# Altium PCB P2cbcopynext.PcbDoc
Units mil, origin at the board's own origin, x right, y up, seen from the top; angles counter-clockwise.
Board outline 1574.8 x 1456.69 mil, 4 copper layers (Top Layer, Layer 1, Layer 2, Bottom Layer), stack 23.756 mil thick; 64 components, 49 nets, 255 pads, 114 vias.
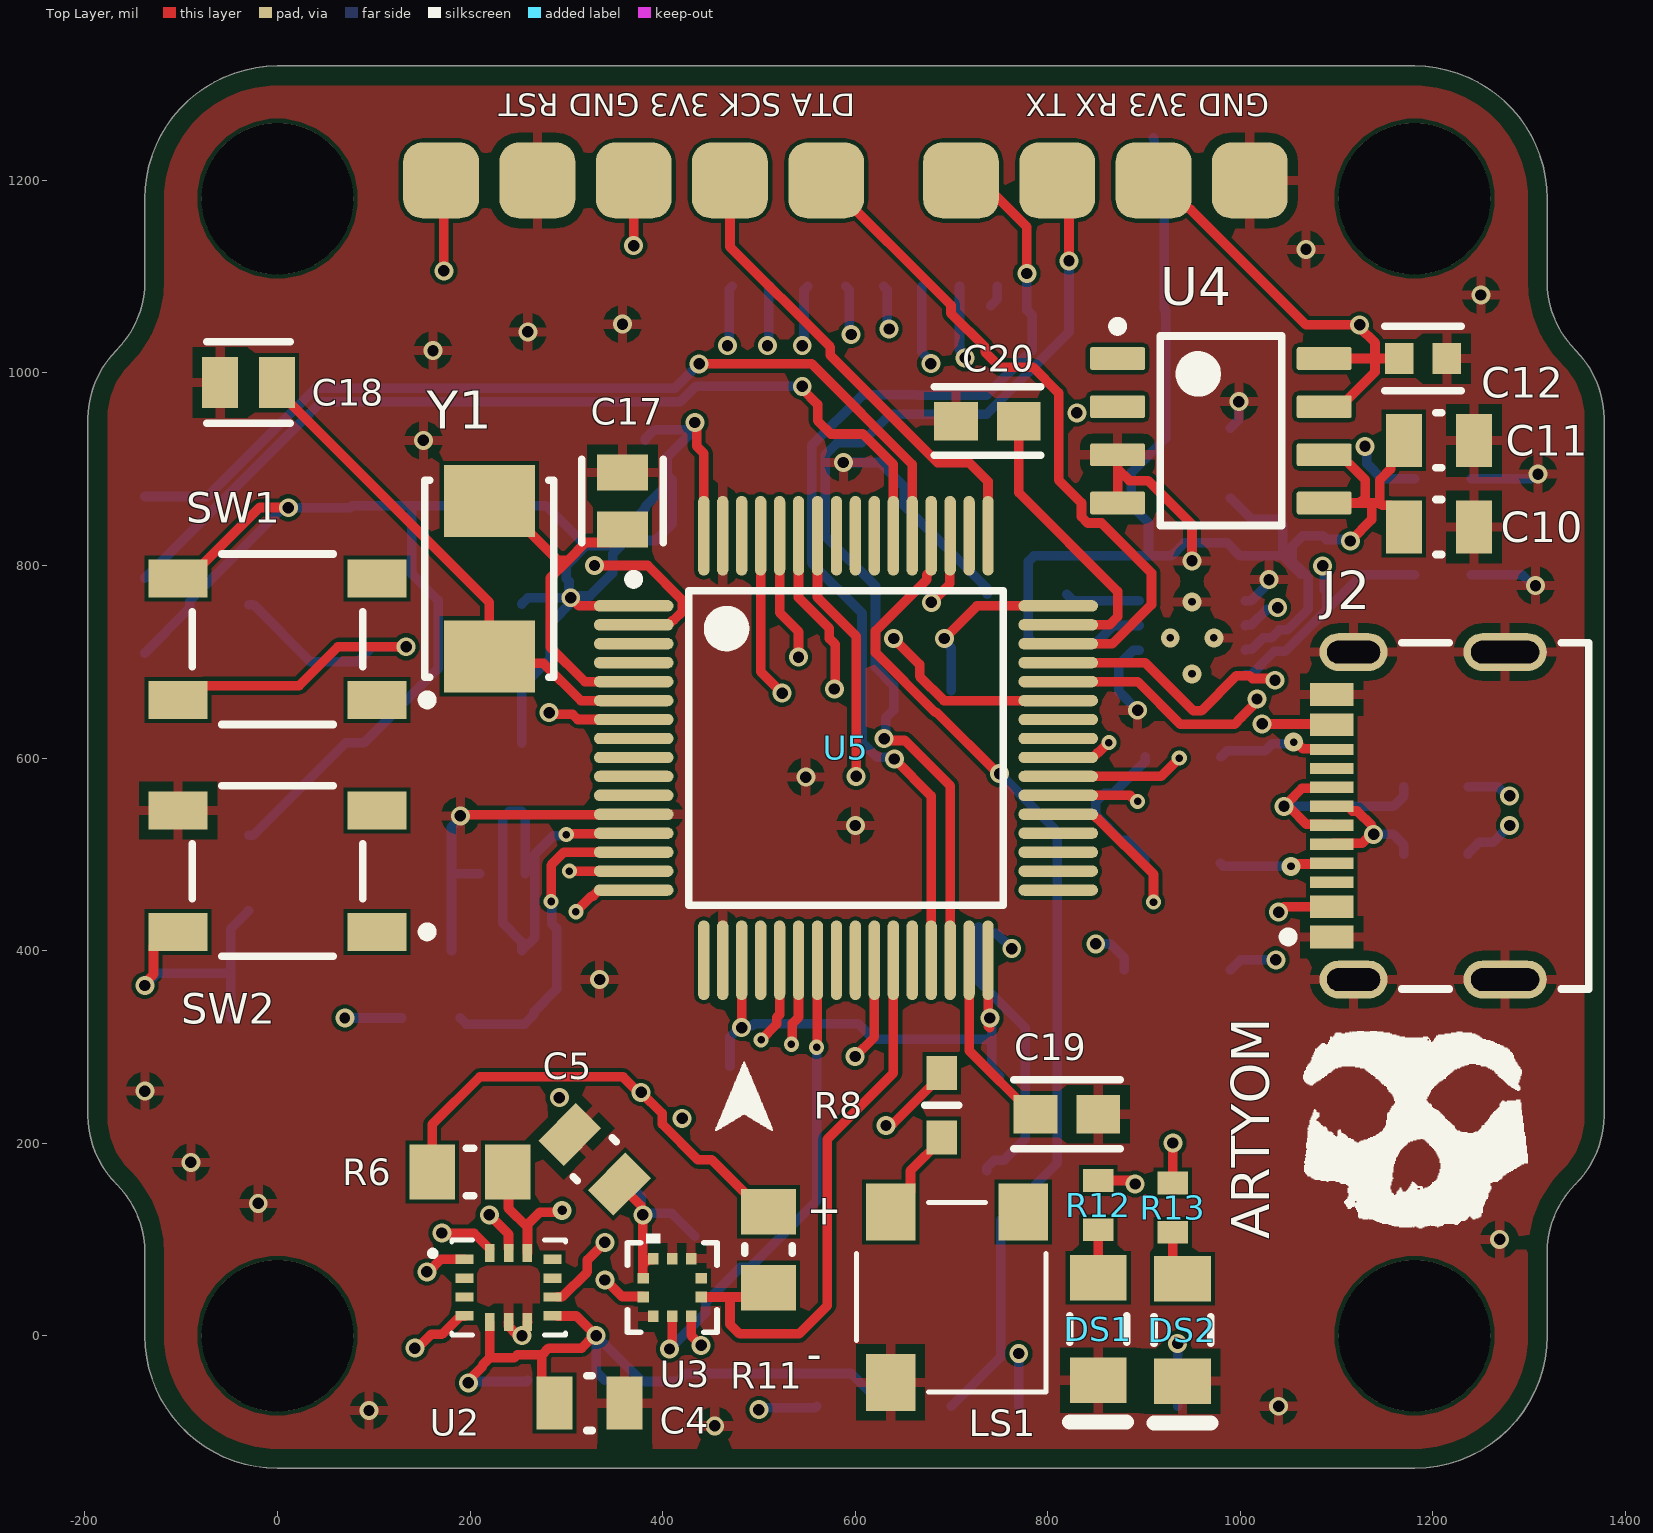
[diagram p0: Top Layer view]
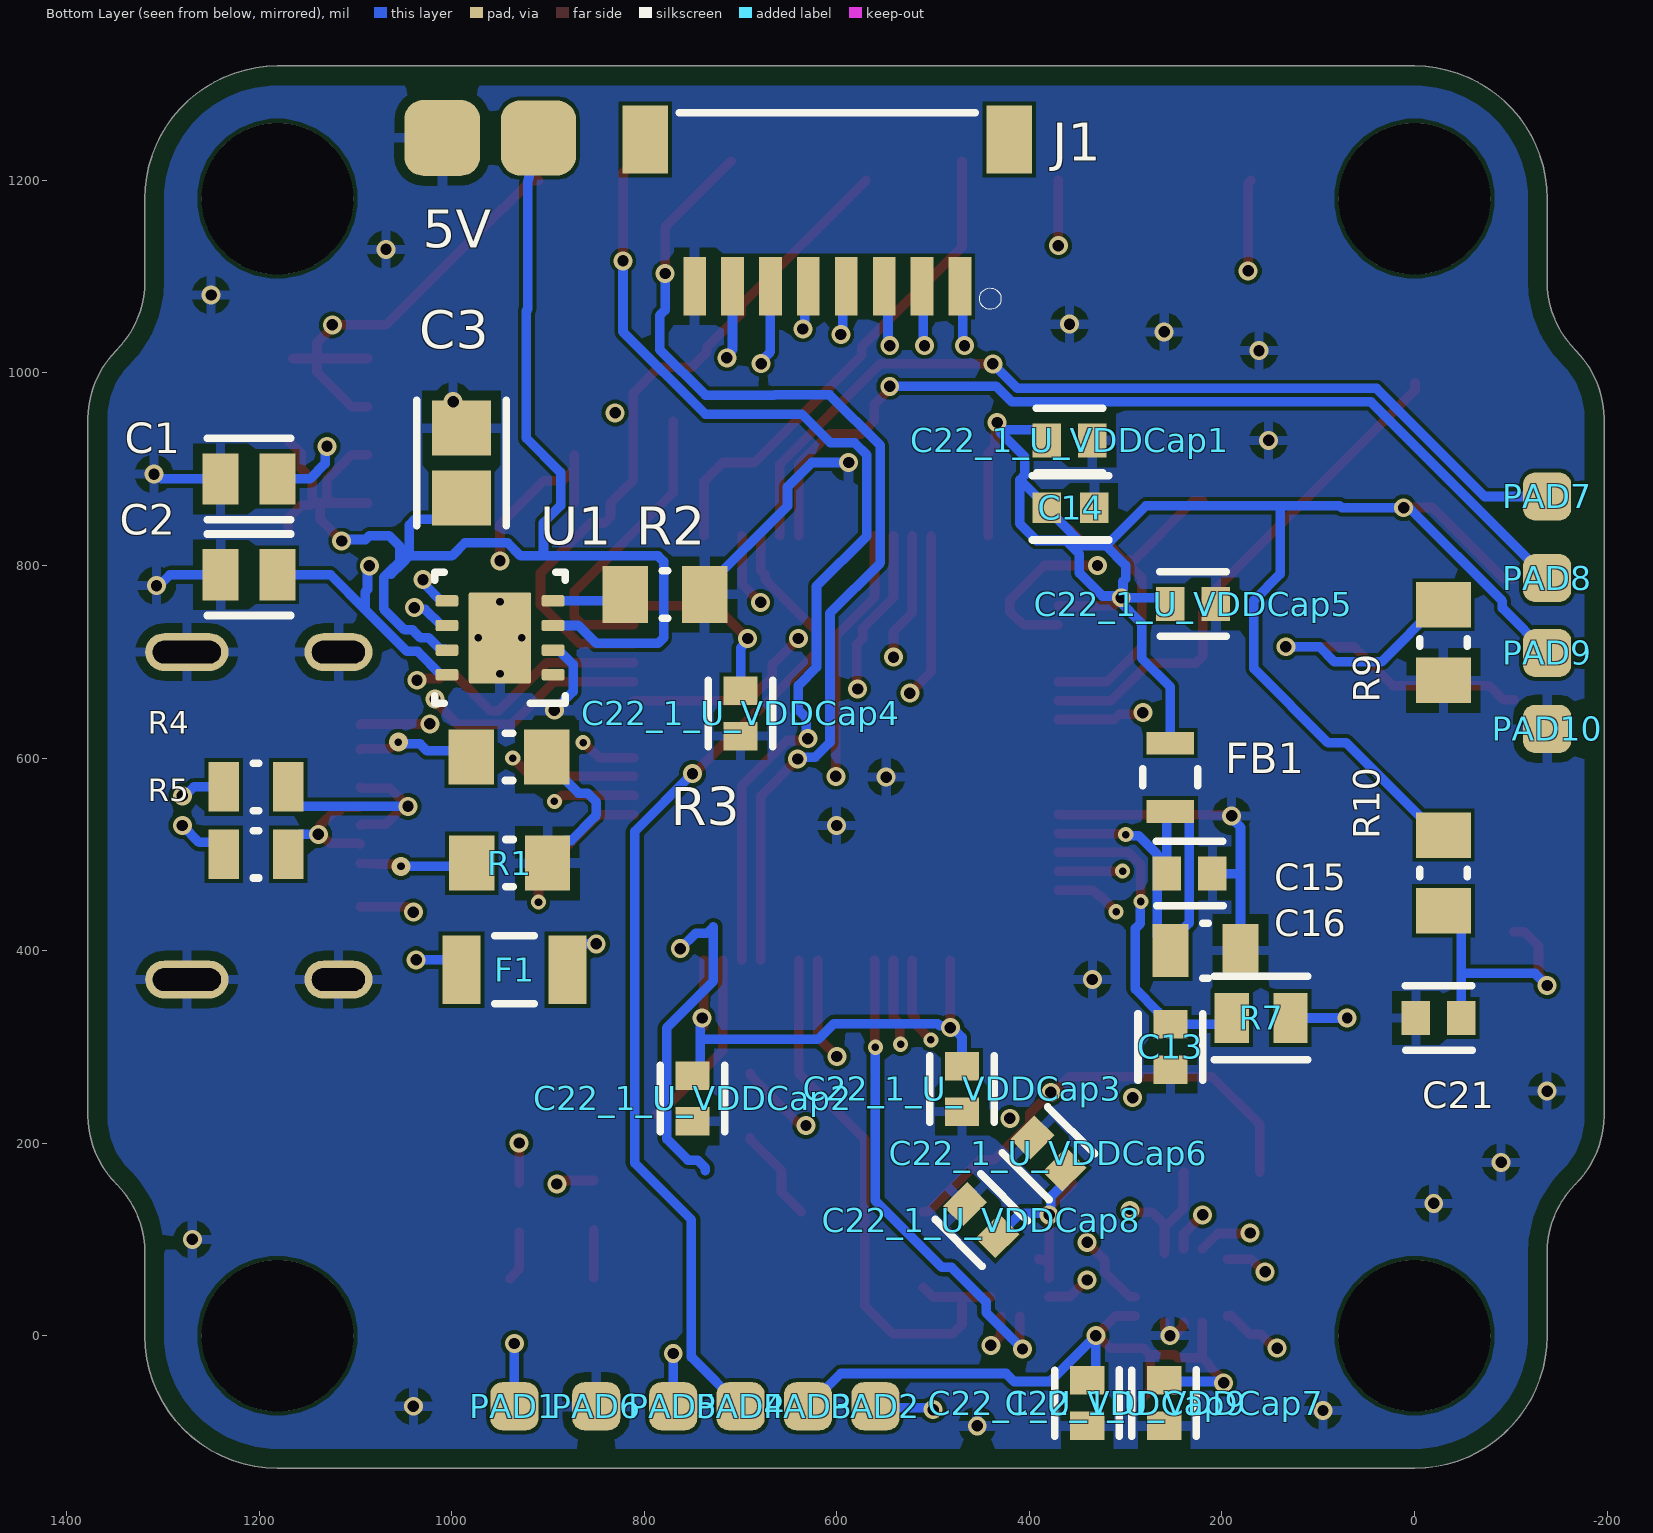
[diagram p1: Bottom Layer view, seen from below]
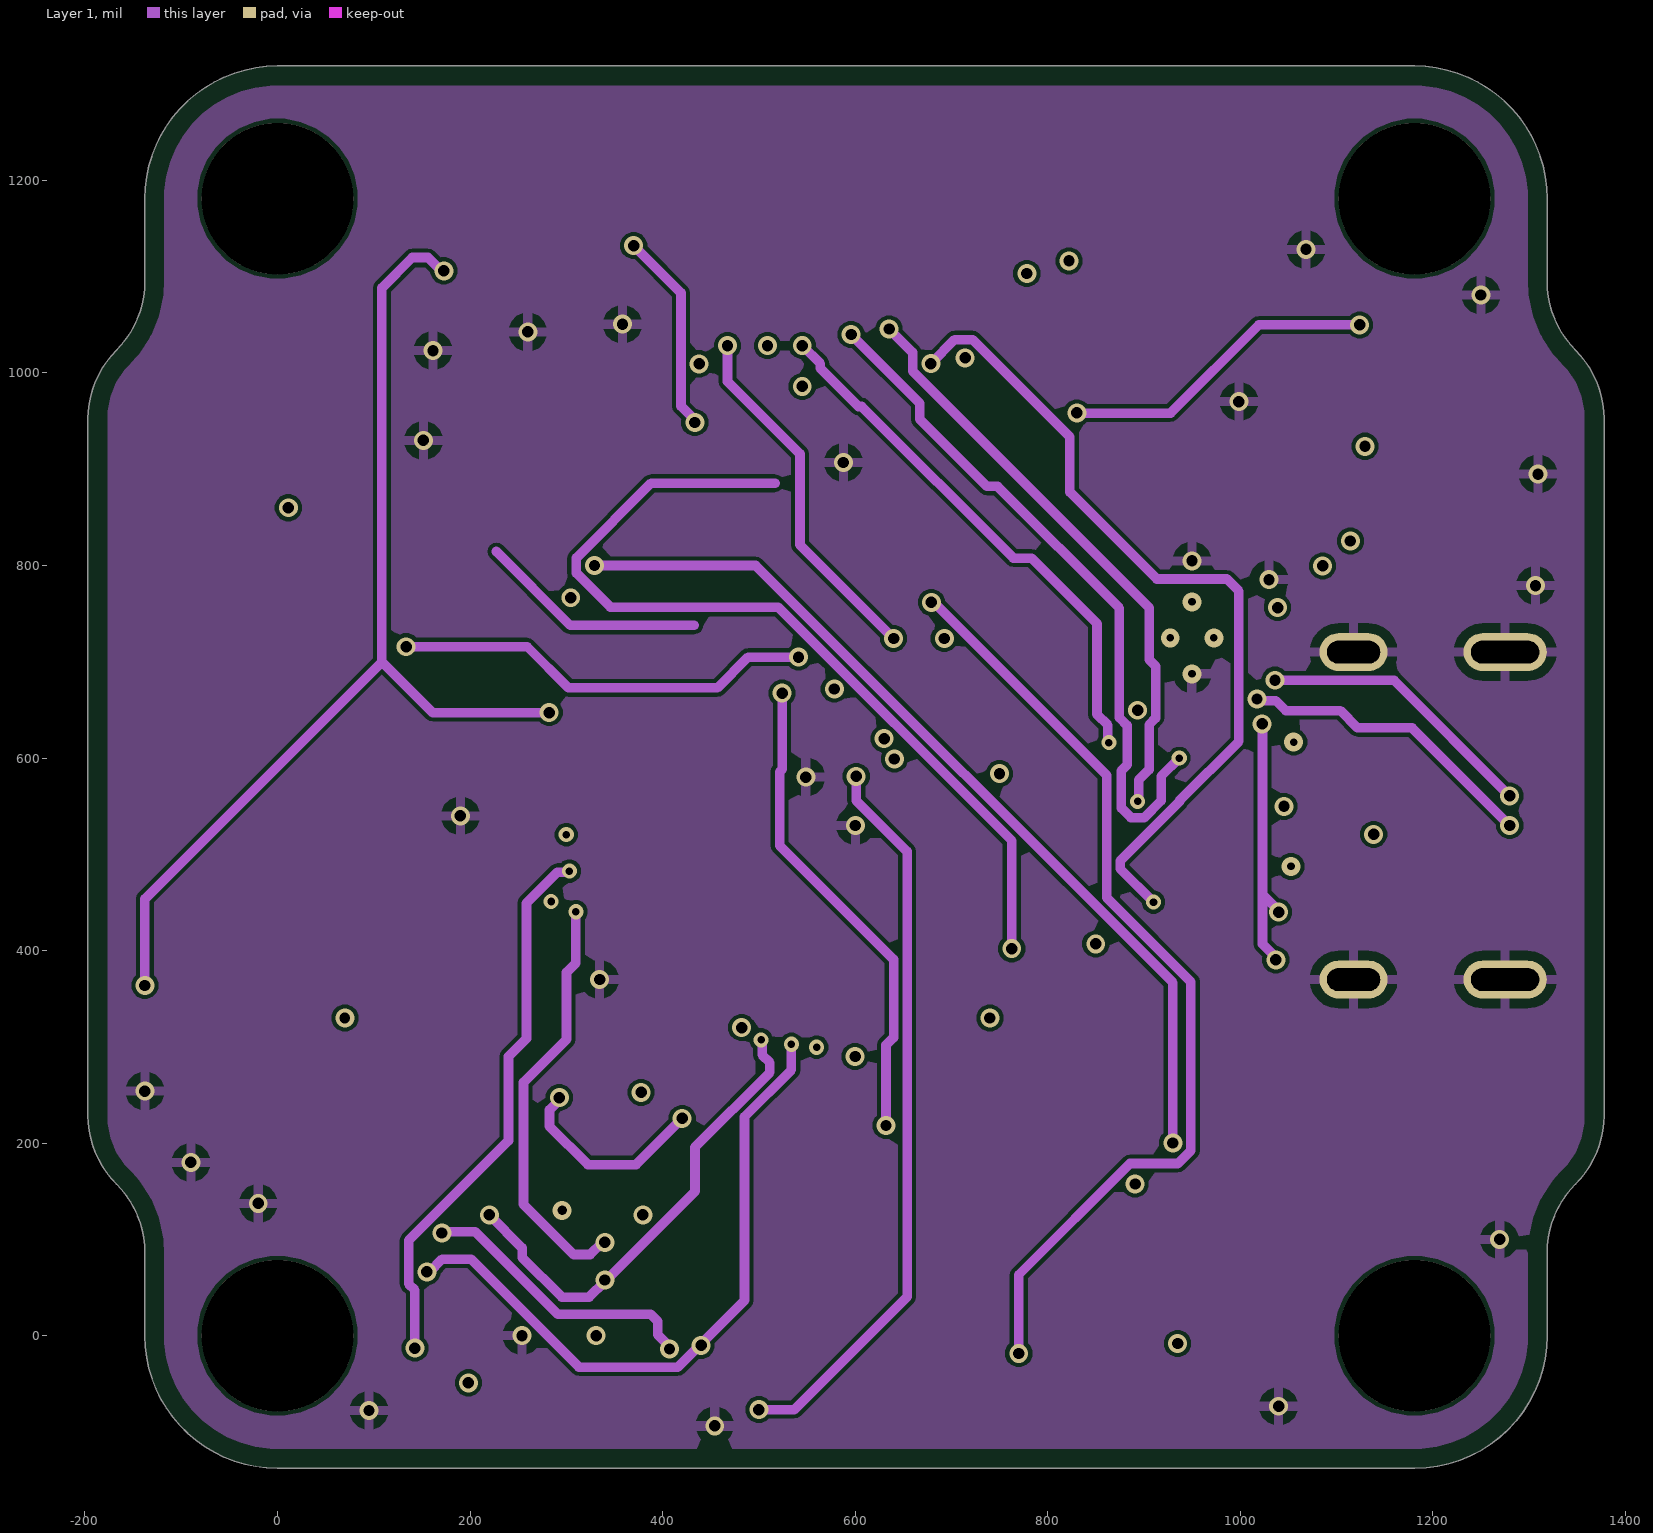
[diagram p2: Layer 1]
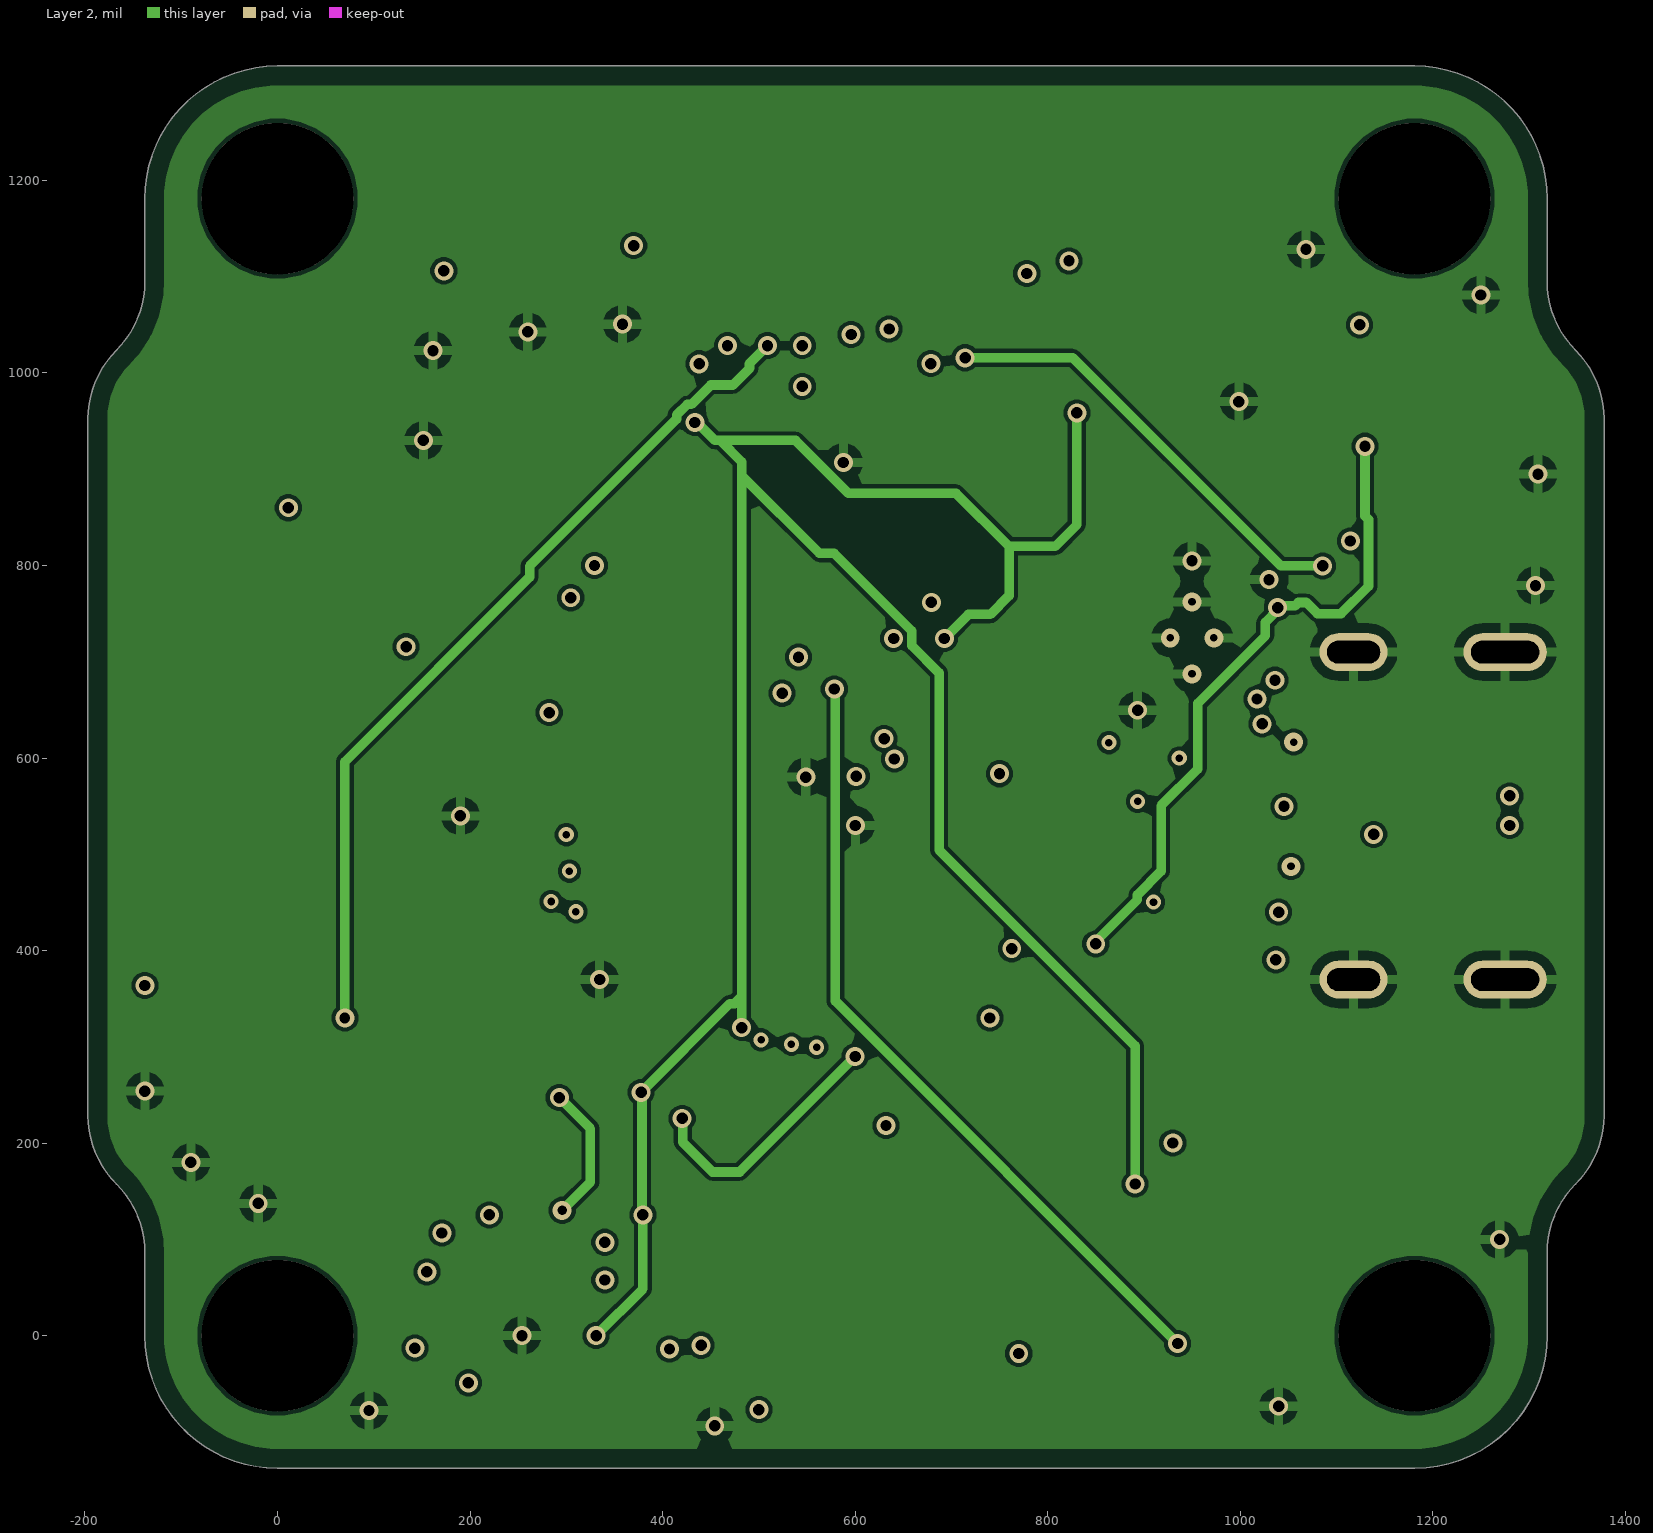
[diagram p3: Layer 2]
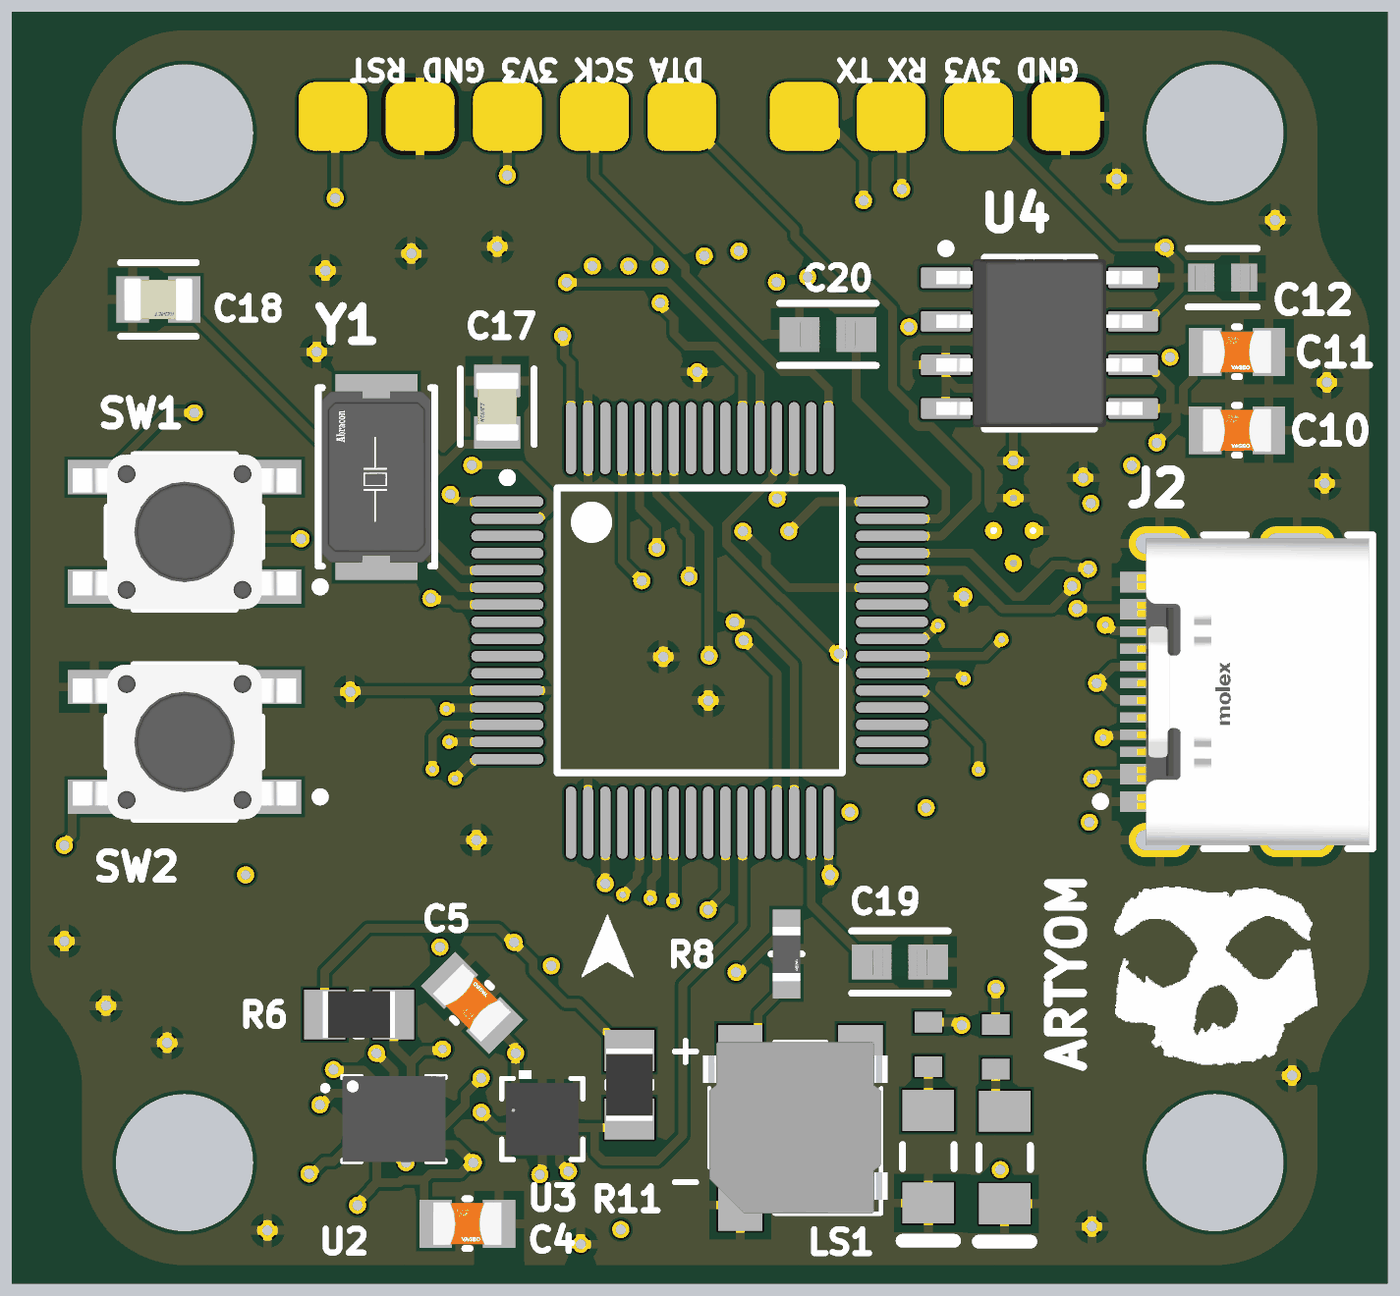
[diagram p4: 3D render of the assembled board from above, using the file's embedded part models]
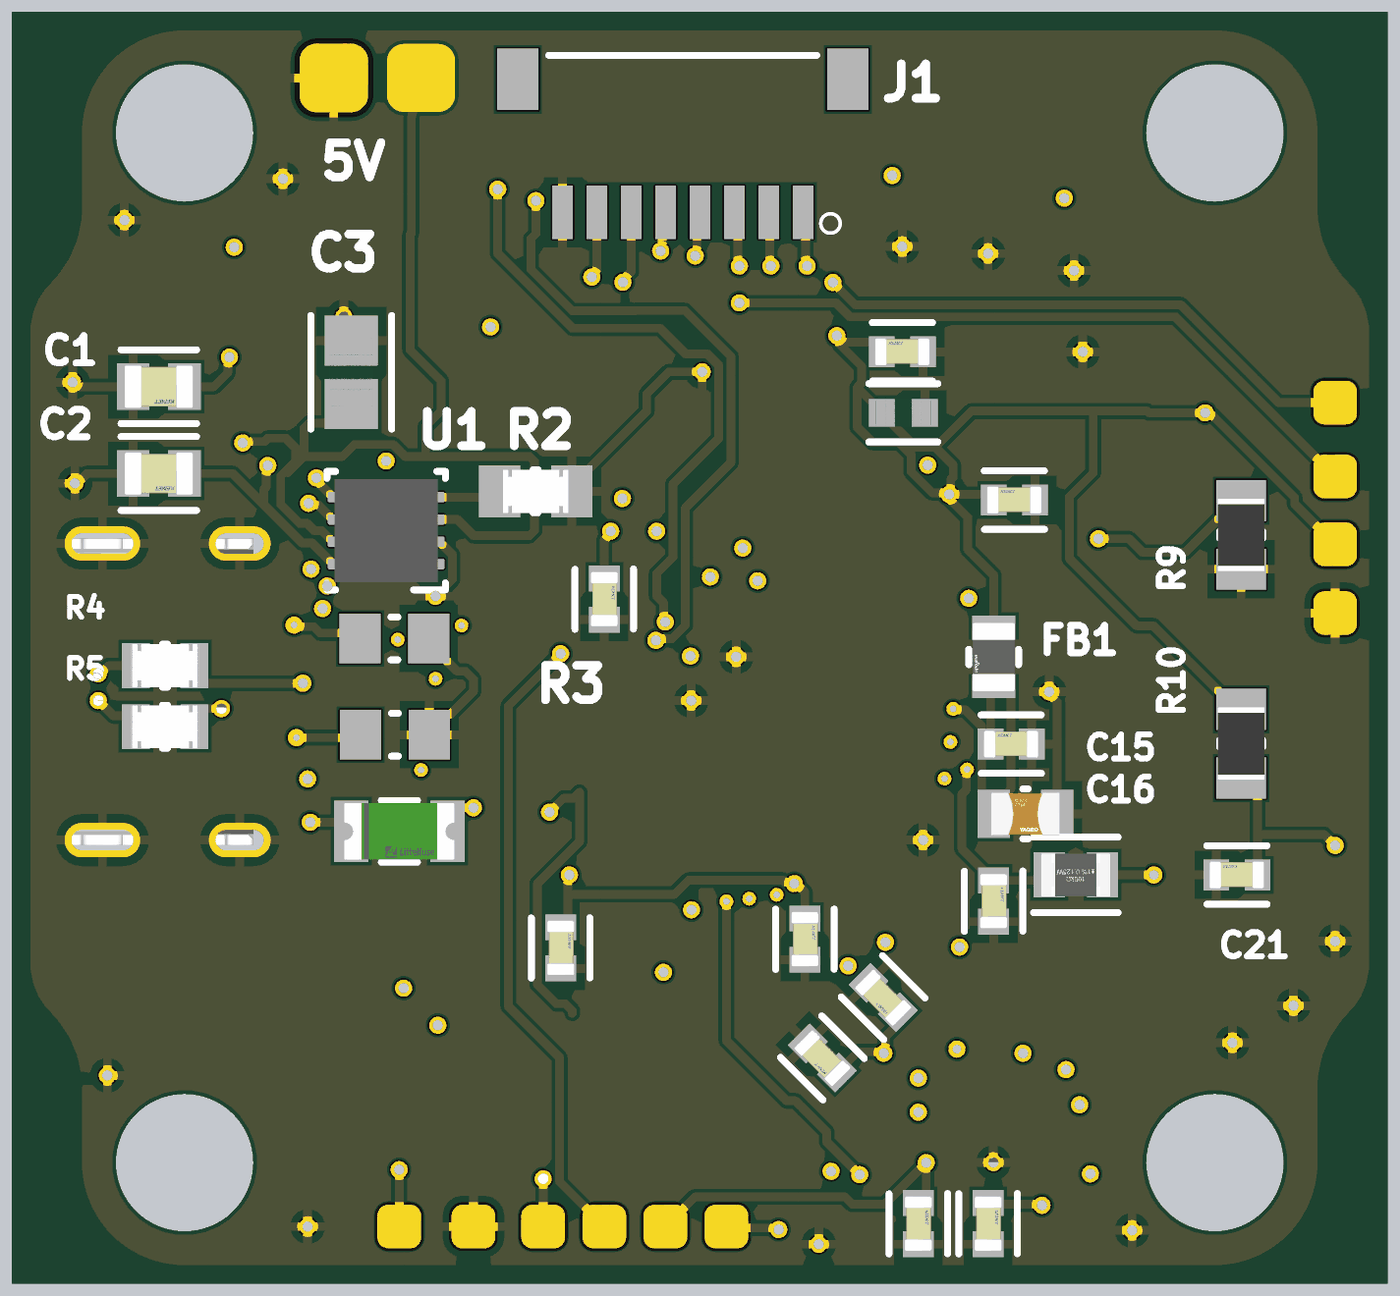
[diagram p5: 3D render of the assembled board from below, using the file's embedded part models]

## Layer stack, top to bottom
Top Solder: solder mask 0.4, Solder Resist, Dk 3.5
Top Layer: signal copper 1.4
Dielectric 2: prepreg 2.8, PP-006, Dk 4.1
Layer 1: signal copper 1.378
Dielectric 1: dielectric 12.6, FR-4, Dk 4.8
Layer 2: signal copper 1.378
Dielectric 3: prepreg 2.8, PP-006, Dk 4.1
Bottom Layer: signal copper 1.4
Bottom Solder: solder mask 0.4, Solder Resist, Dk 3.5

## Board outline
-196.85,228.77 ccw(c-96.04,228.77) -167.32,157.48 cw(c-238.61,86.19) -137.8,86.19 -137.8,0 ccw(c0,0) 0,-137.8 1181.1,-137.8 ccw(c1181.1,0) 1318.9,0 1318.9,86.19 cw(c1419.71,86.19) 1348.43,157.48 ccw(c1277.14,228.77) 1377.95,228.77 1377.95,952.34 ccw(c1277.14,952.34) 1348.43,1023.62 cw(c1419.71,1094.91) 1318.9,1094.91 1318.9,1181.1 ccw(c1181.1,1181.1) 1181.1,1318.9 -0.17,1318.9 0,1318.9 ccw(c0,1181.1) -137.8,1181.1 -137.8,1094.91 cw(c-238.61,1094.91) -167.32,1023.62 ccw(c-96.04,952.34) -196.85,952.34

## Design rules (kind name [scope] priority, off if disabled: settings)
BoardOutlineClearance [All] p1: gap=20 ignorepadtopadclearanceinfootprint=FALSE
Clearance [All] p1: gap=4 ignorepadtopadclearanceinfootprint=FALSE
HoleSize [All] p1: absolutevalues=TRUE maxlimit=196.85 minlimit=1 maxpercent=80.000 minpercent=20.000
MinimumSolderMaskSliver [All] p1: minsoldermaskwidth=2.01
PolygonConnect [All] p1: connectstyle=Relief reliefconductorwidth=10 reliefentries=4 polygonreliefangle="90 Angle" airgapwidth=10
RoutingVias [All] p1: holewidth=28 width=50 viastyle="Through Hole" minholewidth=2 minwidth=2 maxholewidth=55 maxwidth=111
SilkToSolderMaskClearance [IsPad] p1: minsilkscreentomaskgap=3 clearancetoexposedcopper=TRUE
SolderMaskExpansion [All] p1: expansion=2 istentingtop=FALSE
SupplyNets "Schematic Supply Nets_1" [InNet('GND')] p1: voltage=0.000
SupplyNets "Schematic Supply Nets" [InNet('3V3')] p2: voltage=0.000
Width [All] p1: maxlimit=10 minlimit=10 preferedwidth=10
27 further rules are at their usual default settings.

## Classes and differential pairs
channel class VDDCap: U_VDDCap1 U_VDDCap2 U_VDDCap3 U_VDDCap4 U_VDDCap5 U_VDDCap6 U_VDDCap7 U_VDDCap8 U_VDDCap9
net class SBA[1..7]: SBA1 SBA2 SBA3 SBA4 SBA5 SBA6 SBA7
net class MNET[1..4]: MNET1 MNET2 MNET3 MNET4
component class U_VDDCap9: C22_1_U_VDDCap9
component class U_VDDCap8: C22_1_U_VDDCap8
component class U_VDDCap7: C22_1_U_VDDCap7
component class U_VDDCap6: C22_1_U_VDDCap6
component class U_VDDCap5: C22_1_U_VDDCap5 C221
component class U_VDDCap4: C22_1_U_VDDCap4
component class U_VDDCap3: C22_1_U_VDDCap3
component class U_VDDCap2: C22_1_U_VDDCap2
component class U_VDDCap1: C22_1_U_VDDCap1
component class U_USBC5VSchDoc: C1 C2 C3 F1 J1 J2 R1 R2 R3 R4 R5 U1
component class U_Sensors: C4 C5 R6 R11 U2 U3
component class U_mcu: C13 C14 C15 C16 C17 C18 C19 C20 C21 DS2 FB1 LS1 PAD1 PAD2 PAD3 PAD4 PAD5 PAD6 PAD7 PAD8 PAD9 PAD10 R7 R8 R9 R10 R13 SW1 SW2 U5 Y1
component class U_LDO: C10 C11 C12 DS1 R12 U4

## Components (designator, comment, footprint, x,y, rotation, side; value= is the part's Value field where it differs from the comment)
C1 ".10uF" FP-C0805C-DN-MFG 1210.63,890 r0 bottom value="0.10 μF"
C2 ".10uF" FP-C0805C-DN-MFG 1210.63,790.4 r0 bottom value="0.10 μF"
C3 "22uF" FP-CL21-IPC_A 990,906.45 r90 bottom
C4 "1uf" FP-CC0805-0_85-MFG 324.22,-70 r0 top value="1 uF"
C5 "1uf" FP-CC0805-0_85-MFG 329.45,183.23 r135 top value="1 uF"
C10 "1uf" FP-CC0805-0_85-MFG 1206.42,840 r0 top value="1 uF"
C11 "0.1uf" FP-CC0805-0_85-MFG 1206.42,930 r0 top value="100 nF"
C12 "4.7uf" FP-CL10-IPC_C 1190,1015 r0 top
C13 ".1uF" FP-C0603C-CF-MFG 253.62,300 r270 bottom value="0.10 μF"
C14 "4.7uf" FP-CL10-IPC_C 357.24,860 r180 bottom
C15 ".1uF" FP-C0603C-CF-MFG 233.62,480 r180 bottom value="0.10 μF"
C16 "1UF" FP-CC0805-0_85-MFG 217.2,400 r180 bottom value="1 uF"
C17 "22pF" FP-C0805C-DN-MFG 358.43,867.1 r90 top value="22 pF"
C18 "22pF" FP-C0805C-DN-MFG -30,990 r180 top value="22 pF"
C19 "2.2uf" FP-CL10-IPC_A 820,230 r0 top
C20 "2.2uf" FP-CL10-IPC_A 737.44,950 r180 top
C21 ".1uF" FP-C0603C-CF-MFG -25.08,330 r180 bottom value="0.10 μF"
C22_1_U_VDDCap1 ".1uF" FP-C0603C-CF-MFG 358.31,930 r180 bottom value="0.10 μF" (schematic designator C22_1)
C22_1_U_VDDCap2 ".1uF" FP-C0603C-CF-MFG 750,246.38 r270 bottom value="0.10 μF" (schematic designator C22_1)
C22_1_U_VDDCap3 ".1uF" FP-C0603C-CF-MFG 470,256.38 r270 bottom value="0.10 μF" (schematic designator C22_1)
C22_1_U_VDDCap4 ".1uF" FP-C0603C-CF-MFG 700,646.38 r270 bottom value="0.10 μF" (schematic designator C22_1)
C22_1_U_VDDCap5 ".1uF" FP-C0603C-CF-MFG 230,760 r180 bottom value="0.10 μF" (schematic designator C22_1)
C22_1_U_VDDCap6 ".1uF" FP-C0603C-CF-MFG 380.34,189.23 r45 bottom value="0.10 μF" (schematic designator C22_1)
C22_1_U_VDDCap7 ".1uF" FP-C0603C-CF-MFG 260,-70 r270 bottom value="0.10 μF" (schematic designator C22_1)
C22_1_U_VDDCap8 ".1uF" FP-C0603C-CF-MFG 450,120 r45 bottom value="0.10 μF" (schematic designator C22_1)
C22_1_U_VDDCap9 ".1uF" FP-C0603C-CF-MFG 340,-70 r270 bottom value="0.10 μF" (schematic designator C22_1)
DS1 "LED" LUMX-SML-LX1206IC_V 852.56,6.85 r270 top
DS2 "LED" LUMX-SML-LX1206IC_V 940,5.87 r270 top
F1 "Polyfuse" FP-1206L-MFG 934.88,380 r180 bottom value=0.04-0.21Ω
FB1 "FB600Ohm" FP-BLM21-0_2-t0_85-e0_5-MFG 253.62,580 r270 bottom
J1 "8Pin" JST_SM08B-SRSS-TB 610,1277.99 r0 bottom
J2 "217179-0001" FP-2171790001-MFG 1230,540 r90 top
LS1 "Speaker" XDCR_CMT-0525-75-SMT-TR 700,40 r0 top
PAD1 "sw" PCBComponent_1 935.07,-73.32 r90 bottom
PAD2 "sw" PCBComponent_1 560,-73.32 r90 bottom
PAD3 "sw" PCBComponent_1 630,-73.32 r90 bottom
PAD4 "sw" PCBComponent_1 700,-73.32 r90 bottom
PAD5 "sw" PCBComponent_1 770,-73.32 r90 bottom
PAD6 "sw" PCBComponent_1 850,-73.32 r90 bottom
PAD7 "sw" PCBComponent_1 -137.8,871.74 r90 bottom
PAD8 "sw" PCBComponent_1 -137.8,786.99 r90 bottom
PAD9 "sw" PCBComponent_1 -137.8,709.18 r90 bottom
PAD10 "sw" PCBComponent_1 -137.8,630.36 r90 bottom
R1 "5.1k" RESC2013X60X35ML10T20 940,490.79 r180 bottom
R2 "402Ohm" FP-CRCW0805-e3-IPC_A 778.63,770 r180 bottom
R3 "5.1k" RESC2013X60X35ML10T20 940.63,601.26 r180 bottom
R4 "22k Ohm" FP-CRCW0805-e3-IPC_C 1203.5,570 r0 bottom
R5 "22k Ohm" FP-CRCW0805-e3-IPC_C 1203.5,500 r0 bottom
R6 "10Kohm" RESC2013X60X35ML10T20 200,170 r0 top
R7 "CRGCQ0805F220R" FP-CRGCQ0805-IPC_C 159.45,330 r0 bottom value=220Ω
R8 "100Ohm" FP-RC0603-0_55-MFG 690,239.21 r270 top
R9 "10Kohm" RESC2013X60X35ML10T20 -30,720 r90 bottom
R10 "10Kohm" RESC2013X60X35ML10T20 -30,480.63 r270 bottom
R11 "10Kohm" RESC2013X60X35ML10T20 510,89.37 r270 top
R12 "300Ohm" RESC1608X55X25LL10T15 852.56,135.59 r270 top
R13 "300ohm" RESC1608X55X25LL10T15 930,132.99 r90 top
SW1 "Tact" FP-PTS647SM38SMTR2LFS-MFG 0,723.4 r180 top
SW2 "Tact" FP-PTS647SM38SMTR2LFS-MFG 0,482.49 r180 top
U1 "TPS2113ADRBR" DRB0008B_V 950,724.88 r0 bottom
U2 "BMI270" XDCR_BMI270 240,50 r0 top
U3 "BMP384" LGA10_2.0X2.0X0.95_BOS 410,50 r0 top
U4 "TPS76633DR" D0008A_N 980,940 r0 top
U5 "STM32F405RGT6" STM-LQFP64_M 590.47,610.47 r0 top
Y1 "ABM3-8.000MHZ-D2Y-T" FP-ABM3-MFG 220,786.39 r90 top

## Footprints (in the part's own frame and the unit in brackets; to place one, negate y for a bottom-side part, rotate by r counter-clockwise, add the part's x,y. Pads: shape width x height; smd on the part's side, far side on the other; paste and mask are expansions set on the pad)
D0008A_N [mm] "SOIC, 8-Leads, Body 5x4mm, Pitch 1.27mm, IPC Medium Density"
  rrect17% 1.45x0.6 smd: 1(-2.725,1.905) 2(-2.725,0.635) 3(-2.725,-0.635) 4(-2.725,-1.905) 5(2.725,-1.905) 6(2.725,-0.635) 7(2.725,0.635) 8(2.725,1.905)
  silkscreen extent -2.85,-2.5 1.6,2.88, body extent -3,-2.45 3,2.45, height 1.63
DRB0008B_V [mm] "SON, 8-Leads, Body 3x3mm, Pitch 0.65mm, Thermal Pad 2.4x1.65mm, TI Recommended"
  rrect33% 0.6x0.3 smd: 1(-1.4,0.975) 2(-1.4,0.325) 3(-1.4,-0.325) 4(-1.4,-0.975) 5(1.4,-0.975) 6(1.4,-0.325) 7(1.4,0.325) 8(1.4,0.975)
  rrect6% 1.65x2.4 smd paste-1.2: 9(0,0)
  silkscreen extent -1.73,-1.73 1.73,1.73, body extent -1.5,-1.5 1.5,1.5, height 0.96
FP-1206L-MFG [mm]
  rect 1x1.8 smd paste+0 mask+0: 1(-1.4,0) 2(1.4,0)
  silkscreen extent -0.53,-0.9 0.53,0.9, body extent -1.6,-0.82 1.6,0.82, height 1.25
FP-2171790001-MFG [mm]
  rrect100% 1x1.8 hole 0.6 slot 1.4 at 90 deg paste-2539.97 mask+0: 1(-4.32,2.85) 2(4.32,2.85)
  rrect100% 1x2.2 hole 0.6 slot 1.8 at 90 deg paste-2539.97 mask+0: 3(-4.32,-1.15) 4(4.32,-1.15)
  rect 0.6x1.15 smd paste+0 mask+0: A1-B12(-3.2,3.425) A4-B9(-2.4,3.425) B1-A12(3.2,3.425) B4-A9(2.4,3.425)
  rect 0.3x1.15 smd paste+0 mask+0: A5(-1.25,3.425) A6(-0.25,3.425) A7(0.25,3.425) A8(1.25,3.425) B5(1.75,3.425) B6(0.75,3.425) B7(-0.75,3.425) B8(-1.75,3.425)
  silkscreen extent -4.57,-3.35 4.57,4.7, body extent -4.92,-3.45 4.92,4.1, height 0.25
FP-ABM3-MFG [mm]
  rect 1.9x2.4 smd paste+0 mask+0: 1(-2.05,0) 2(2.05,0)
  silkscreen extent -2.6,-1.7 2.6,1.7, body extent -3.1,-1.8 3.1,1.8, height 0.25
FP-BLM21-0_2-t0_85-e0_5-MFG [mm]
  rect 0.6x1.25 smd paste+0 mask+0: 1(-0.9,0) 2(0.9,0)
  silkscreen extent -0.23,-0.72 0.23,0.72, body extent -1,-0.63 1,0.63, height 1.05
FP-C0603C-CF-MFG [mm]
  rect 0.75x0.9 smd paste+0 mask+0: 1(-0.6,0) 2(0.6,0)
  silkscreen extent -0.87,-0.85 0.88,0.85, body extent -0.8,-0.4 0.8,0.4, height 0.87
FP-C0805C-DN-MFG [mm]
  rect 0.95x1.35 smd paste+0 mask+0: 1(-0.75,0) 2(0.75,0)
  silkscreen extent -1.1,-1.07 1.1,1.07, body extent -1,-0.63 1,0.63, height 0.88
FP-CC0805-0_85-MFG [mm]
  rect 0.95x1.4 smd paste+0 mask+0: 1(-0.925,0) 2(0.925,0)
  silkscreen extent -0.08,-0.72 0.08,0.72, body extent -1.6,-1.05 1.6,1.05, height 0.25
FP-CL10-IPC_A [mil]
  rect 45.6x39.85 smd paste+0 mask+0: 1(-32.56,0) 2(32.56,0)
  silkscreen extent -55,-36 55,36, body extent -75,-40 75,40, height 10
FP-CL10-IPC_C [mil]
  rect 29.85x31.97 smd paste+0 mask+0: 1(-24.68,0) 2(24.68,0)
  silkscreen extent -40,-33 40,33, body extent -44,-22 44,22, height 10
FP-CL21-IPC_A [mil]
  rect 57.27x61.27 smd paste+0 mask+0: 1(-36.45,0) 2(36.45,0)
  silkscreen extent -65,-46 65,46, body extent -39,-25 39,25, height 57
FP-CRCW0805-e3-IPC_A [mil]
  rect 47.5x59.38 smd paste+0 mask+0: 1(-41.37,0) 2(41.37,0)
  silkscreen extent -3,-25 3,25, body extent -39,-25 39,25, height 20
FP-CRCW0805-e3-IPC_C [mil]
  rect 31.75x51.5 smd paste+0 mask+0: 1(-33.5,0) 2(33.5,0)
  silkscreen extent -3,-25 3,25, body extent -39,-25 39,25, height 20
FP-CRGCQ0805-IPC_C [mil]
  rect 35.67x51.57 smd paste+0 mask+0: 1(-30.55,0) 2(30.55,0)
  silkscreen extent -48,-43 48,43, body extent -39,-25 39,25, height 26
FP-PTS647SM38SMTR2LFS-MFG [mm]
  rect 1.55x1 smd paste+0 mask+0: 1(-2.625,1.6) 2(2.625,1.6) 3(-2.625,-1.6) 4(2.625,-1.6)
  silkscreen extent -4.08,-2.25 2.25,2.25, body extent -3.5,-2.42 3.5,2.42, height 0.25
FP-RC0603-0_55-MFG [mm]
  rect 0.9x0.8 smd paste+0 mask+0: 1(-0.85,0) 2(0.85,0)
  silkscreen extent 0,-0.45 0,0.45, body extent -1.4,-0.55 1.4,0.55, height 0.25
JST_SM08B-SRSS-TB [mm]
  rect 0.6x1.55 smd: 1(-3.5,4.775) 2(-2.5,4.775) 3(-1.5,4.775) 4(-0.5,4.775) 5(0.5,4.775) 6(1.5,4.775) 7(2.5,4.775) 8(3.5,4.775)
  rect 1.2x1.8 smd: P1(-4.8,0.9) P2(4.8,0.9)
  silkscreen extent -4.58,0.2 3.9,5.38
LGA10_2.0X2.0X0.95_BOS [mil]
  rect 12x11 smd paste+0 mask+0: 1(-30,9.84) 2(-30,-9.84) 6(30,-9.84) 7(30,9.84)
  rect 11x12 smd paste+0 mask+0: 3(-19.69,-30) 4(0,-30) 5(19.69,-30) 8(19.69,30) 9(0,30) 10(-19.69,30)
  silkscreen extent -46,-46 46,56, body extent -41,-41 41,41, height 39
LUMX-SML-LX1206IC_V [mm] "SMD, 2-Leads, Body 3.2x1.5mm"
  rect 1.2x1.5 smd: 1(-1.35,0) 2(1.35,0)
  silkscreen extent -0.35,-0.75 2.45,0.75, body extent -1.6,-0.8 1.6,0.8, height 1.1
PCBComponent_1 [mil]
  rrect50% 50x50 smd paste-99999 mask+3: 44(0,0)
RESC1608X55X25LL10T15 [mm] "Chip Resistor, 2-Leads, Body 1.60x0.80mm, IPC High Density"
  rect 0.6x0.8 smd: 1(-0.65,0) 2(0.65,0)
  body extent -0.85,-0.45 0.85,0.45, height 0.55
RESC2013X60X35ML10T20 [mm] "Chip Resistor, 2-Leads, Body 2.00x1.25mm, IPC Low Density"
  rect 1.2x1.45 smd: 1(-1,0) 2(1,0)
  silkscreen extent -0.1,-0.63 0.1,0.63, body extent -1.05,-0.67 1.05,0.67, height 0.6
STM-LQFP64_M [mm] "Thin QFP, 64-Leads, Body 10x10mm, Pitch 0.5mm, IPC Low Density"
  oval 2.1x0.3 smd: 1(-5.6,3.75) 2(-5.6,3.25) 3(-5.6,2.75) 4(-5.6,2.25) 5(-5.6,1.75) 6(-5.6,1.25) 7(-5.6,0.75) 8(-5.6,0.25) 9(-5.6,-0.25) 10(-5.6,-0.75) 11(-5.6,-1.25) 12(-5.6,-1.75) 13(-5.6,-2.25) 14(-5.6,-2.75) 15(-5.6,-3.25) 16(-5.6,-3.75) 33(5.6,-3.75) 34(5.6,-3.25) 35(5.6,-2.75) 36(5.6,-2.25) 37(5.6,-1.75) 38(5.6,-1.25) 39(5.6,-0.75) 40(5.6,-0.25) 41(5.6,0.25) 42(5.6,0.75) 43(5.6,1.25) 44(5.6,1.75) 45(5.6,2.25) 46(5.6,2.75) 47(5.6,3.25) 48(5.6,3.75)
  oval 0.3x2.1 smd: 17(-3.75,-5.6) 18(-3.25,-5.6) 19(-2.75,-5.6) 20(-2.25,-5.6) 21(-1.75,-5.6) 22(-1.25,-5.6) 23(-0.75,-5.6) 24(-0.25,-5.6) 25(0.25,-5.6) 26(0.75,-5.6) 27(1.25,-5.6) 28(1.75,-5.6) 29(2.25,-5.6) 30(2.75,-5.6) 31(3.25,-5.6) 32(3.75,-5.6) 49(3.75,5.6) 50(3.25,5.6) 51(2.75,5.6) 52(2.25,5.6) 53(1.75,5.6) 54(1.25,5.6) 55(0.75,5.6) 56(0.25,5.6) 57(-0.25,5.6) 58(-0.75,5.6) 59(-1.25,5.6) 60(-1.75,5.6) 61(-2.25,5.6) 62(-2.75,5.6) 63(-3.25,5.6) 64(-3.75,5.6)
  silkscreen extent -5.72,-4.15 4.15,4.57, body extent -5,-5 5,5, height 1.6
XDCR_BMI270 [mm]
  rect 0.475x0.25 smd: 1(-1.162,0.75) 2(-1.162,0.25) 3(-1.162,-0.25) 4(-1.162,-0.75) 8(1.162,-0.75) 9(1.162,-0.25) 10(1.162,0.25) 11(1.162,0.75)
  rect 0.25x0.475 smd: 5(-0.5,-0.913) 6(0,-0.913) 7(0.5,-0.913) 12(0.5,0.913) 13(0,0.913) 14(-0.5,0.913)
  silkscreen extent -2.07,-1.25 1.5,1.25, body extent -1.5,-1.25 1.5,1.25, height 0.87
XDCR_CMT-0525-75-SMT-TR [mm]
  rect 1.3x1.5 smd: 1(1.9,2.25) N(-1.6,-2.25) P(-1.6,2.25)
  silkscreen extent -2.5,-2.5 2.5,2.5, body extent -2.68,-2.5 2.68,2.5, height 2.5

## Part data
C1 C2: library part CMP-2007-00279-2, "CAP CER 0.1UF 50V X7R 0805", Capacitance="0.10 μF", Manufacturer=KEMET, Manufacturer Part Number=C0805C104K5RACTU, Package=C0805C-DN, Temperature="-55°C to +125°C", Temperature Characteristic=X7R, Temperature Coefficient=30ppm/°C, Temperature Range High=+125°C, Temperature Range Low=-55°C, Tolerance=0.1, Voltage Rating="50 V"
C3: library part CMP-13271-000185-1, "CL21 Series 0805 22uF 6.3V ±20% Tolerance X5R Multilayer Ceramic Chip Capacitor", Case Code (Imperial)=0805, Case Code (Metric)=2012, Dielectric=X5R, Max Operating Temperature=85°C, Min Operating Temperature=-55°C, Package Quantity=2000, Tolerance=20%, Voltage Rating=6.3V
C4 C5 C10 C16: library part CMP-2100-03605-2, "CAP CER 1UF 25V X7R 0805", Capacitance="1 uF", Manufacturer=Yageo, Manufacturer Part Number=CC0805KKX7R8BB105, Package=CC0805-0.85, Temperature="-30°C to +85°C", Temperature Characteristic=X7R, Temperature Range High=+85°C, Temperature Range Low=-30°C, Tolerance=0.1, Voltage Rating="25 V"
C11: library part CMP-2007-01272-2, "CC0805 100 nF X7R 10.00% 50 V", Capacitance="100 nF", Manufacturer=Yageo, Manufacturer Part Number=CC0805KPX7R9BB104, Package=CC0805-0.85, Temperature="-30°C to +85°C", Temperature Characteristic=X7R, Temperature Range High=+85°C, Temperature Range Low=-30°C, Tolerance=0.1, Voltage Rating="50 V"
C12 C14: library part CMP-13271-003017-1, "Cap Ceramic 4.7uF 10V X5R ±10% Pad SMD 0603 +85°C T/R", Capacitance=4.7uF, Case Code (Imperial)=0603, Case Code (Metric)=1608, Dielectric=X5R, Max Operating Temperature=85°C, Min Operating Temperature=-55°C, Package Quantity=1, Tolerance=10%, Voltage Rating=10V
C13 C15 C21 C22_1_U_VDDCap1 C22_1_U_VDDCap2 C22_1_U_VDDCap3 C22_1_U_VDDCap4 C22_1_U_VDDCap5 C22_1_U_VDDCap6 C22_1_U_VDDCap7 C22_1_U_VDDCap8 C22_1_U_VDDCap9: library part CMP-2006-03061-2, "CAP CER 0.1UF 50V X7R 0603", Capacitance="0.10 μF", Manufacturer=KEMET, Manufacturer Part Number=C0603C104K5RACTU, Package=C0603C-CF, Temperature="-55°C to +125°C", Temperature Characteristic=X7R, Temperature Coefficient=30ppm/°C, Temperature Range High=+125°C, Temperature Range Low=-55°C, Tolerance=0.1, Voltage Rating="50 V"
C17 C18: library part CMP-2007-00048-2, "Capacitor; Ceramic; Cap; 22.0pF; Tol 5%; SMT; Vol-Rtg 50V; C0G; Tape and Reel", Capacitance="22 pF", Manufacturer=KEMET, Manufacturer Part Number=C0805C220J5GACTU, Package=C0805C-DN, Temperature="-55°C to +125°C", Temperature Characteristic=C0G, Temperature Coefficient=30ppm/°C, Temperature Range High=+125°C, Temperature Range Low=-55°C, Tolerance=0.05, Voltage Rating="50 V"
C19 C20: library part CMP-13271-003582-1, "Cap Ceramic 2.2uF 10V X7R ±10% Pad SMD 0603 +125°C T/R", Capacitance=2.2uF, Case Code (Imperial)=0603, Case Code (Metric)=1608, Dielectric=X7R, Max Operating Temperature=125°C, Min Operating Temperature=-55°C, Package Quantity=1, Tolerance=10%, Voltage Rating=10V
DS1 DS2: library part CMP-2000-07123-1, "LED Red, 65 mW, -40 to 85 degC, 2-Pin SMD, RoHS, Tape and Reel / SML-LX1206IC-TR", Color=Red, Manufacturer=Lumex, Operating Temperature=-25to85C, Package Description="2-Pin Surface Mount Device, Body 3.2 x 1.5 mm", Package Reference=SML-LX1206IC, Part No=SML-LX1206IC-TR, Reverse Voltage=5(Min)V, Supplier_Package=SMD
F1: library part CMP-08606-000042-1, "PTC RESET FUSE 8V 1.1A 1206", Ambient Temperature Range High=+85°C, Ambient Temperature Range Low=-40°C, Current Rating=100A, Hold Current=1.1A, Manufacturer=Littelfuse, Manufacturer Part Number=1206L110THYR, Package=1206L, Resistance=0.04-0.21Ω, Temperature="-40°C to +85°C", Trip Current=2.2A, Voltage Rating=8V
FB1: library part CMP-0686-00639-3, "Chip Ferrite Bead, 0805, 600Ω @ 100MHz, 0.2Ω, 25%, 700mA", Case Code (Imperial)=0805, Case Code (Metric)=2012, Current Rating=600mA, DC Current=200mA, DC Resistance (DCR)=210mR, ESR (Equivalent Series Resistance)=600R, Frequency=100MHz, Max Current Rating=700mA, Max Operating Temperature=125°C, Min Operating Temperature=-55°C, Package Quantity=1, Temperature Coefficient=10ppm/°C, Tolerance=25%
J1: library part SM08B-SRSS-TB, "SH Series 8 Position 1 mm Pitch Surface Mount Side Entry Shrouded Header / SM08B-SRSS-TB", Package=None
J2: library part CMP-04767-000028-2, "CONN RCP USB2.0 TYP C 24P SMD RA", Current Rating=1.25A, Max Operating Temperature=85°C, Min Operating Temperature=-40°C, Voltage Rating=30V
LS1: library part CMT-0525-75-SMT-TR, "5 mm, 3 Vo-p, 75 dB, Surface Mount (SMT), Magnetic Audio Transducer Buzzer / CMT-0525-75-SMT-TR", Package="CUI Devices"
PAD1 PAD2 PAD3 PAD4 PAD5 PAD6 PAD7 PAD8 PAD9 PAD10: library part Comp
R1 R3: library part CMP-2001-01390-1, Manufacturer=Yageo, Part Number=RC0805JR-075K1L
R2: library part CMP-2001-03902-2, "RES Thick Film, 402Ω, 1%, 0.125W, 100ppm/°C, 0805", Case Code (Imperial)=0805, Case Code (Metric)=2012, Max Operating Temperature=155°C, Max Power Dissipation=125mW, Min Operating Temperature=-55°C, Package Quantity=10, Resistance=402R, Temperature Coefficient=100ppm/°C, Tolerance=1%, Voltage Rating=150V
R4 R5: library part CMP-2001-03692-2, "RES Thick Film, 22Ω, 1%, 0.125W, 100ppm/°C, 0805", Case Code (Imperial)=0805, Case Code (Metric)=2012, Max Operating Temperature=155°C, Max Power Dissipation=125mW, Min Operating Temperature=-55°C, Package Quantity=5000, Resistance=22R, Temperature Coefficient=100ppm/°C, Tolerance=1%, Voltage Rating=150V
R6 R9 R10 R11: library part CMP-2000-05025-1, "Chip Resistor, 10 KOhm, +/- 5%, 0.125 W, -55 to 155 degC, 0805 (2012 Metric), RoHS, Tape and Reel", Manufacturer=Yageo, Package Description="2-Pin Surface Mounted Device, Body 2 x 1.25 mm", Package Reference=805, Power Rating=250mW, Resistance=10kohm, Resistance Tolerance=±5%, Resistor Case Style=0805[2012Metric], Resistor Element Type=ThickFilm, Temperature Coefficient=±100ppm/degC, Voltage Rating=150V
R7: library part CMP-03211-009876-1, "CRGCQ0805 220Ω 0.125W ±100ppm/°C 1% 150V", Ambient Temperature Range High=+70°C, Manufacturer="TE Connectivity", Package=CRGCQ0805, Power Rating=0.125W, Resistance=220Ω, Temperature="-55°C to +155°C", Temperature Coefficient=±100ppm/°C, Temperature Range High=+155°C, Temperature Range Low=-55°C, Tolerance=0.01, Voltage Rating=150V
R8: library part CMP-2100-03663-2, Case Code (Imperial)=0603, Max Operating Temperature=155°C, Min Operating Temperature=-55°C, Power Rating=100mW, Resistance=100Ω, Temperature Coefficient=100ppm/°C, Tolerance=1%, Voltage Rating=50V
R12 R13: library part CMP-2000-06958-1, "Chip Resistor, 330 Ohm, +/- 5%, 50 V, -55 to 155 degC, 0603 (1608 Metric), -40 to 155 degC, RoHS, Tape and Reel / RC0603JR-07330RL", Manufacturer=Yageo, Package Description="2-Pin Surface Mount Device, Body 1.6 x 0.8 mm", Package Reference=0603, Power Rating=100mW, Resistance=330ohm, Resistance Tolerance=±5%, Resistor Case Style=0603[1608Metric], Resistor Element Type=ThickFilm, Temperature Coefficient=±100ppm/°C, Voltage Rating=50V
SW1 SW2: library part CMP-10040-000031-1, "TACT 4.5 X 4.5, 3.8 MM H, 1.8N,  / PTS647SM38SMTR2LFS", Max Operating Temperature=70°C, Min Operating Temperature=-20°C, Operating Force=180gf, Ratings=IP40
U1: library part CMP-0339-00015-2, "Dual In / Single Out Autoswitching Power Mux, 2.8 to 5.5 V, -40 to 85 degC, 9-pin SON (DRB), Green (RoHS & no Sb/Br)", IN1 Output Current(Max)(A)=1.25, IN1, IN2 Input Voltage(Max)(V)=5.5, IN1, IN2 Input Voltage(Min)(V)=2.8, Manufacturer="Texas Instruments"
U2: "Accelerometer, Gyroscope, 6 Axis Sensor IÂ²C, SPI Output", Package="LGA-14 Bosch Sensortec"
U3: "Description", Manufacturer_Name="Bosch Sensortec"
U4: library part CMP-0394-00013-2, "Single Output LDO, 250 mA, Fixed 3.3 V Output, 2.7 to 10 V Input, with Low IQ, 8-pin SOIC (D), -40 to 125 degC, Green (RoHS & no Sb/Br)", Manufacturer="Texas Instruments", Power Good=TRUE
U5: library part CMP-0243-00019-3, "ARM Cortex-M4 32-bit MCU+FPU, 210 DMIPS, 1024 kB Flash, 192 kB Internal RAM, 51 I/Os, 64-pin LQFP, -40 to 85 degC, Tray", I/Os (High Current)=51, Manufacturer=STMicroelectronics, Operating Frequency(F) (Processor speed) (MHz)=168, Supply Voltage(Vcc) max (V)=3.6, Supply Voltage(Vcc) min (V)=1.8
Y1: library part CMP-2000-05033-2, "Crystal 8MHz ±20ppm 18pF SMD-2 5mm x 3.2mm", Case/Package=CSMD, ESR (Equivalent Series Resistance)=140R, Frequency=8MHz, Frequency Stability=30ppm, Frequency Tolerance=20ppm, Load Capacitance=18pF, Max Operating Temperature=85°C, Min Operating Temperature=-40°C, Package Quantity=1000, Resistor Type=Ceramic, Series Resistance=500R

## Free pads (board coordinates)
  round 157.48 hole 157.48 unplated paste-99999 mask+0: 5(1181.1,1181.1) 6(0,1181.1) 7(0,0) 8(1181.1,0)
  rrect50% 78.74x78.74 smd paste-99999 mask+2: 30(170,1200) 33(470,1200) 35(710,1200) 36(810,1200) 40(570,1200) 41(370,1200)
  rrect50% 78.74x78.74 smd paste-99999 mask+5: 31(270,1200) 38(1010,1200)
  rrect50% 78.74x78.74 smd paste-99999 mask+1.18: 37(910,1200)
  rrect50% 78x78 smd far side paste-99999 mask+0: 42(910,1244.14)
  rrect50% 78.74x78.74 smd far side paste-99999 mask+5.91: 43(1010,1244.14)

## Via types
v1: diameter 19.68, hole 11.81, Top Layer to Bottom Layer, 95 vias
v2: diameter 15.75, hole 7.87, Top Layer to Bottom Layer, 11 vias
v3: diameter 19.68, hole 7.87, Top Layer to Bottom Layer, 6 vias
v4: diameter 19.68, hole 10, Top Layer to Bottom Layer, 1 vias
v5: diameter 19.68, hole 11, Top Layer to Bottom Layer, 1 vias

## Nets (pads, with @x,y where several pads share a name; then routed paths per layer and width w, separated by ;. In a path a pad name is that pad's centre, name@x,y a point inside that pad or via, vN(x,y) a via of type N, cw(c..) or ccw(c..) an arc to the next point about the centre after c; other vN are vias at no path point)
3V3: C4.1 C5.1 C12.1 C14.1 C22_1_U_VDDCap1.1 C22_1_U_VDDCap2.1 C22_1_U_VDDCap3.1 C22_1_U_VDDCap4.1 C22_1_U_VDDCap5.1 C22_1_U_VDDCap6.1 C22_1_U_VDDCap7.1 C22_1_U_VDDCap8.1 C22_1_U_VDDCap9.1 FB1.1 PAD3.44 PAD9.44 pad.37 pad.41 R6.1 R10.1 R11.1 R12.1 SW1.4 U2.5 U2.8 U3.1 U3.10 U4.7 U4.8 U5.1 U5.19 U5.32 U5.48 U5.64 | length 8042.2
  Top Layer w10: SW1.4 -92.52,786.39 -18.6,860.31 10.93,860.31 v1(11.24,860) ; R6.1 160.63,219.37 210.11,268.85 359.01,268.85 375.1,252.75 v1(377.73,252.75) 399.67,230.81 399.67,219.73 436.8,182.61 451.21,182.61 505.08,128.74 R11.1 ; v1(198.32,-48.98) 198.32,-46.36 213.24,-31.43 213.24,-30.16 220.31,-23.09 ; U2.5 220.31,-23.09 ; C4.1 274.68,-56.87 274.68,-20 ; U2.8@290.12,20.47 310.51,20.47 v1(330.98,0) 329,0 316.07,-12.93 281.75,-12.93 274.68,-20 ; v1(304.62,766.5) 313.01,758.11 U5.1 ; C5.1 377.73,134.96 377.73,127.28 v1(379.58,125.43) 379.41,125.26 379.41,73.14 ; v1(370,1132.26) pad.41 ; U3.1 379.91,59.84 379.41,60.34 379.41,73.14 ; U3.10 390.31,79.5 389.81,79 385.27,79 379.41,73.14 ; v1(433.47,948.52) 435.32,946.67 435.32,924.07 442.83,916.55 U5.64 ; v1(482.2,320) U5.19 ; v1(692.64,724.26) 726.5,758.11 U5.48 ; U5.32 738.46,389.65 738.46,321.54 740,320 ; R12.1 887.18,161.18 v1(890.88,157.48) ; pad.37 917.95,1200 947.98,1169.97 948.39,1169.97 1068.36,1050 v1(1124.14,1050) 1124.14,1047.38 1140,1031.52 1140,1015 ; U4.7 1104.02,965 1140,1000.98 1140,1015 ; U4.8 1140,1015 ; C12.1 1140,1015 ; 220.31,-23.09 245.95,-23.09 249.04,-20 274.68,-20
  Layer 1 w10: v1(370,1132.26) 419.09,1083.17 419.09,965.52 433.47,951.15 v1(433.47,948.52) ; v1(830.33,958.51) 830.51,958.33 927.63,958.33 1019.3,1050 v1(1124.14,1050)
  Layer 2 w10: v1(330.98,0) 379.58,48.6 v1(379.58,125.43) 378.65,126.35 378.65,251.83 v1(377.73,252.75) 469.81,344.84 474.84,344.84 482.2,352.2 ; v1(433.47,948.52) 435.81,948.52 454.33,930 460,930 ; v1(482.2,320) 482.2,352.2 ; v1(692.64,724.26) 717.59,749.2 740.49,749.2 760,768.71 760,820 ; v1(830.33,958.51) 830.33,842.37 807.96,820 760,820 ; v1(890.88,157.48) 890.88,300.9 687.28,504.5 687.28,688.35 658.84,716.79 658.84,732.06 578.16,812.75 562.89,812.75 482.2,893.43 482.2,907.8 ; 460,930 482.2,907.8 ; 460,930 538.15,930 593.15,875 705,875 760,820 ; 482.2,352.2 482.2,907.8
  Bottom Layer w10: PAD9.44 -91.33,755.64 -91.33,762.93 3.88,858.15 9.39,858.15 v1(11.24,860) 75.64,860 77.73,862.09 139.51,862.09 ; R10.1 -25.08,520 70.74,615.82 89.64,615.82 166.84,693.02 166.84,763.89 139.51,791.22 139.51,862.09 ; v1(198.32,-48.98) 199.62,-47.68 258.7,-47.68 C22_1_U_VDDCap7.1 ; FB1.1 253.62,673.9 283.39,703.66 283.39,739.97 306.99,763.57 306.99,764.39 309.09,766.5 309.09,768.35 324.24,768.35 348.08,792.2 348.08,811.94 362.14,826 392.65,826 410,843.35 410,889.04 409.95,889.09 ; C22_1_U_VDDCap5.1 260.12,766.5 v1(304.62,766.5) 302.77,768.35 302.77,783.57 300,786.34 300,800 320.56,820.56 ; C22_1_U_VDDCap9.1 330.98,-37.36 v1(330.98,0) 378.66,-47.68 415.91,-47.68 424.27,-39.32 596,-39.32 PAD3.44 ; C22_1_U_VDDCap6.1 363.64,158.72 377.73,144.64 377.73,127.28 v1(379.58,125.43) 381.32,127.17 409.42,127.17 C22_1_U_VDDCap8.1 ; C14.1 381.93,858.94 372,849.01 371.55,849.01 343.1,820.56 320.56,820.56 ; C14.1@381.93,861.06 409.95,889.09 ; C22_1_U_VDDCap1.1 381.93,931.43 391.69,941.19 v1@430.39,941.19 ; v1(433.47,948.52) 433.47,945.9 430.39,942.83 v1@430.39,941.19 ; C22_1_U_VDDCap3.1 470,310 480,320 v1(482.2,320) 484.06,321.85 493.09,321.85 495.34,324.11 603.14,324.11 619.43,307.82 741.85,307.82 ; v1(692.64,724.26) 692.64,721.63 700,714.28 C22_1_U_VDDCap4.1 ; v1(740,330) 741.85,328.15 741.85,307.82 ; C22_1_U_VDDCap2.1 741.85,278.15 741.85,307.82 ; 139.51,862.09 279.03,862.09 320.56,820.56 ; 409.95,889.09 404.94,894.1 404.94,913.15 430.39,938.6 v1@430.39,941.19
5V_RAIL: C3.1 C10.1 C11.1 pad.42 U1.3 U1.7 U4.5 U4.6 | length 1589.9
  Top Layer w10: U4.5 1124.14,865 ; U4.6 1104.02,915 1130,889.02 1130,870.86 1124.14,865 ; v1(1114.47,825.51) 1136.64,847.68 1136.64,865 ; C10.1 1170,848.86 1156.3,862.56 1147.44,862.56 1145,865 ; C11.1 1156.3,916.3 1156.3,900.31 1145,889.02 1145,865 ; 1124.14,865 1136.64,865 ; 1136.64,865 1145,865
  Bottom Layer w10: U1.3 868.5,737.68 849.88,719.07 785.86,719.07 780,724.92 780,804.14 785.86,810 904.74,810 ; pad.42 921.1,1198.35 921.1,1066.02 922.6,1064.52 922.6,932.2 887,896.59 887,862.17 904.74,844.42 904.74,810 ; C3.1 1011.77,848.23 1038.36,848.23 1044.22,842.37 1044.22,810 ; U1.7 1006.02,712.99 1011.93,712.99 1023.82,724.88 1032.44,724.88 1040.74,733.19 1049.06,733.19 1070.85,754.98 1070.85,776.66 1070.85,783.37 1070.85,787.5 1065.05,793.31 1054.01,804.35 1054.01,819.96 1065.05,830.99 1085.7,830.99 1089.63,827.07 1112.9,827.07 v1(1114.47,825.51) ; 1062.98,791.24 1051.94,802.28 1044.22,810 ; 904.74,810 928.54,810 942.2,823.65 986.38,823.65 1000.03,810 1044.22,810
CC1: J2.A5 R1.1 | length 118.3
  Top Layer w10: v3(1052.84,487.45) 1055.46,487.45 1057.9,489.88 1077.52,489.88 1077.52,490 J2.A5
  Bottom Layer w10: R1.1 982.71,487.45 v3(1052.84,487.45)
CC2: J2.B5 R3.1 | length 124.7
  Top Layer w10: v3(1055.6,616.57) 1058.22,616.57 1064.99,609.8 1094.25,609.8 J2.B5
  Bottom Layer w10: R3.1 986.19,607.45 1025.75,607.45 1033.03,614.72 1053.74,614.72 v3(1055.6,616.57)
CURNET: J1.2 R7.1 | length 1015.7
  Layer 2 w10: v5@70,331.98 70,596.18 261.87,788.05 261.87,799.32 414.63,952.07 414.63,956.33 425.66,967.37 429.92,967.37 450.11,987.56 472.97,987.56 490.3,1004.89 490.3,1009.64 v1(509.03,1028.37)
  Bottom Layer w10: v5(70,330) R7.1 ; v1(509.03,1028.37) 510.3,1029.64 510.3,1088.73 J1.2
D+: R4.2 U5.45 | length 603.5
  Top Layer w10: U5.45 901.37,699.06 951.37,649.05 959.65,649.05 996.23,685.63 1009.9,685.63 1012.86,682.67 1034.28,682.67 v1(1036.14,680.82)
  Layer 1 w10: v1(1036.14,680.82) 1159.9,680.82 v1(1280,560.72)
  Bottom Layer w10: R4.2 1268.1,570 1277.38,560.72 v1(1280,560.72)
D-: R5.2 U5.44 | length 610.8
  Top Layer w10: U5.44 893.63,679.37 937.95,635.05 994.12,635.05 1001.53,642.46 1001.53,642.78 1017.53,658.77 v1(1017.53,661.39)
  Layer 1 w10: v1(1017.53,661.39) 1019.38,659.54 1037.06,659.54 1047.37,649.23 1104.07,649.23 1121.91,631.39 1178.61,631.39 v1(1280,530)
  Bottom Layer w10: R5.2 1237,501.56 1247.87,512.43 1262.43,512.43 v1(1280,530)
ESCIN: C2.1 J1.7 U1.8 | length 803.6
  Layer 2 w10: v1(714.25,1015.78) 826.26,1015.78 1042.47,799.58 v1(1085.7,799.58)
  Bottom Layer w10: J1.7 708.43,1024.23 714.25,1018.4 v1(714.25,1015.78) ; U1.8 1011.02,686.5 1035.41,710.88 1046.55,710.88 1090.07,754.4 ; v1(1085.7,799.58) 1087.56,797.73 1087.56,775.11 1090.07,772.59 1090.07,754.4 ; C2.1 1126.07,790.4 1090.07,754.4
GND: C1.2 C2.2 C3.2 C4.2 C5.2 C10.2 C11.2 C12.2 C13.2 C14.2 C15.2 C16.2 C17.2 C18.2 C19.2 C20.2 C21.1 C22_1_U_VDDCap1.2 C22_1_U_VDDCap2.2 C22_1_U_VDDCap3.2 C22_1_U_VDDCap4.2 C22_1_U_VDDCap5.2 C22_1_U_VDDCap6.2 C22_1_U_VDDCap7.2 C22_1_U_VDDCap8.2 C22_1_U_VDDCap9.2 DS1.2 DS2.2 J1.8 J2.1 J2.2 J2.3 J2.4 J2.A1-B12 J2.B1-A12 LS1.N PAD6.44 PAD10.44 pad.31 pad.38 pad.43 R1.2 R2.2 R3.2 R9.1 SW2.4 U1.2 U1.5 U1.9 U2.6 U2.7 U3.3 U3.8 U3.9 U4.3 U4.4 U5.12 U5.18 U5.63 | length 1279.4
  Top Layer w10: v1(190,540) 191.23,541.23 369.65,541.23 U5.12 ; U2.6 240,9.8 247.95,1.85 252.07,1.85 v1(253.92,0) 253.92,2.62 259.61,8.31 259.61,14 U2.7 ; U4.4 872.72,900.4 ; U4.3 872.72,900.4 ; v1(950,804.81) 950,842.54 904.35,888.19 884.93,888.19 872.72,900.4
  Bottom Layer w10: C16.2 180.79,480 ; v1(190,540) 190,537.38 180.79,528.17 180.79,480 ; C15.2 180.79,480 ; v1(587.77,907.02) 626,907.02 651.38,881.65 651.38,861.81 737.26,775.94 R2.2 ; J1.8@740.98,1070 747.8,1076.81 J1.8 ; v1(893.43,649.66) 874.07,669.01 874.07,697.18 888.98,712.09 U1.2 ; R1.2 900.63,495.71 882.01,514.33 875.98,514.33 852.2,538.11 849.88,540.42 849.88,554.51 858.95,563.57 868.5,563.57 901.26,596.34 R3.2 ; C3.2 998.68,951.58 v1(998.68,970.25) ; U1.5 1011.02,763.27 1028.14,780.39 1028.14,783.55 v1(1029.99,785.4) ; C2.2 1292.96,790.4 1304.2,779.16 v1(1306.82,779.16) ; C1.2 1301.79,890 1306.79,895 v1(1309.41,895)
  other v1: 454.19,-93.62 95,-77.74 1040,-73.32 1269.56,100 -20,137.46 -90,180 -137.8,253.95 334.57,370 600.31,530 548.8,580.19 151.55,930 161.55,1023.18 260,1042.75 358.43,1050.66 1250,1081.05 1068.36,1128.36
  other v3: 950,687.48 927.36,724.88 972.64,724.88 950,762.28
MNET1: J1.6 U5.37 | length 1098.8
  Top Layer w10: U5.37@810.6,541.23 847.21,541.23 851.65,536.8 852.55,536.8 910,479.35 v2(910,450.37)
  Layer 1 w10: v1(678.62,1009.78) 703.46,1034.62 722.05,1034.62 823.16,933.52 823.16,876.22 913.41,785.97 986.17,785.97 998.68,773.45 998.68,617.37 937.03,555.72 937.03,554.92 875.38,493.27 875.38,484.99 v2(910,450.37)
  Bottom Layer w10: J1.6 669.06,1021.96 678.62,1012.4 v1(678.62,1009.78)
MNET2: J1.5 U5.38 | length 745.4
  Top Layer w10: U5.38@810.62,560.94 U5.38 885.6,561.26 891.87,554.98 v2(893.43,554.98)
  Layer 1 w10: v1(635.34,1045.65) 659.78,1021.22 659.78,1001.97 905.5,756.26 905.5,702.21 912.27,695.43 912.27,641.39 905.5,634.61 905.5,588.16 894.53,577.2 894.53,556.08 v2(893.43,554.98)
  Bottom Layer w10: J1.5 633.49,1086.2 633.49,1047.51 v1(635.34,1045.65)
MNET3: J1.4 U5.39 | length 910.5
  Top Layer w10: U5.39@811.06,581.06 811.18,580.94 917.78,580.94 v2(936.76,599.92)
  Layer 1 w10: v1(595.82,1040) 667.33,968.49 667.33,951.89 736.99,882.24 748.08,882.24 874.59,755.73 874.59,641.85 882.64,633.8 882.64,592.93 876.56,586.85 876.56,547.99 886.44,538.11 900.42,538.11 918.04,555.73 918.04,581.21 v2(936.76,599.92)
  Bottom Layer w10: J1.4 593.97,1086.35 593.97,1041.85 v1(595.82,1040)
MNET4: J1.3 U5.40 | length 680.7
  Top Layer w10: U5.40@810.71,600.39 846.63,600.39 851.65,605.41 852.55,605.41 863.18,616.04 v2(863.64,616.04)
  Layer 1 w10: v1(545.12,1028.37) 563.85,1009.64 563.85,1004.89 603.51,965.24 606.82,965.24 764.36,807.7 783.25,807.7 851.24,739.71 851.24,645.4 862.54,634.1 862.54,617.14 v2(863.64,616.04)
  Bottom Layer w10: v1(545.12,1028.37) 546.98,1030.22 546.98,1086.03 J1.3
NetC1_1: C1.1 F1.2 U1.6 | length 852.1
  Layer 2 w10: v1(850,407) 850,409.62 893.19,452.81 893.19,457.78 917.91,482.51 917.91,550.63 955.96,588.67 955.96,656.79 1026.05,726.89 1026.05,740.8 1038.89,753.63 v1(1038.89,756.26) 1040.74,758.11 1057,758.11 1060.45,761.55 1068.73,761.55 1080.26,750.03 1104.89,750.03 1133.31,778.45 1133.31,847.79 1129.67,851.43 v1(1129.67,923.83)
  Bottom Layer w10: v1(850,407) 865.08,407 879.76,392.31 F1.2 ; U1.6 1006.02,738.58 1011.93,738.58 1027.75,754.4 1037.04,754.4 v1(1038.89,756.26) ; v1(1129.67,923.83) 1131.52,921.98 1131.52,905.88 1147.4,890 C1.1
NetC13_1: C13.1 R7.2 U5.14 | length 342
  Top Layer w10: v2(284.2,450.96) 284.2,488.74 297.66,502.2 U5.14
  Bottom Layer w10: R7.2 196.38,323.62 256.57,323.62 266.34,333.39 266.34,336.34 290,360 290,422.91 284.83,428.08 284.83,450.33 v2(284.2,450.96)
NetC15_1: C15.1 C16.1 FB1.2 U5.13 | length 451.9
  Top Layer w10: v2(300,520.51) 301.03,521.54 369.65,521.54 U5.13
  Bottom Layer w10: C15.1 257.24,540.94 FB1.2 240.83,544.57 234.02,537.76 234.02,428.46 253.62,408.86 C16.1 267.32,413.7 267.32,500.25 286.49,519.41 298.9,519.41 v2(300,520.51)
NetC17_1: C17.1 U5.5 Y1.2 | length 376.7
  Top Layer w10: Y1.2 229.84,867.1 291.52,805.42 301.6,805.42 ; C17.1 344.72,823.87 320.05,823.87 301.6,805.42 ; U5.5 319.19,679.37 283.16,715.4 283.16,786.98 301.6,805.42
NetC18_1: C18.1 U5.6 Y1.1 | length 544.7
  Top Layer w10: C18.1 -0.47,982.13 220,761.65 Y1.1 227.38,698.3 276.39,698.3 315,659.69 U5.6
NetC19_1: C19.1 U5.31 | length 190.3
  Top Layer w10: U5.31 718.43,296.14 784.57,230 C19.1
NetC20_1: C20.1 U5.47 | length 311
  Top Layer w10: C20.1 770,875.77 872.72,773.05 872.72,746.81 864.34,738.43 U5.47
NetDS1_1: DS1.1 R12.2 | length 50
  Top Layer w10: DS1.1 R12.2
NetDS2_1: DS2.1 R13.1 | length 52.5
  Top Layer w10: R13.1 930,69.02 DS2.1
NetF1_1: F1.1 J2.A4-B9 J2.B4-A9 | length 457.6
  Top Layer w10: v1(1022.87,635.47) 1022.92,635.42 1094.23,635.42 J2.B4-A9 ; v1(1040,440) 1045.51,445.51 J2.A4-B9
  Layer 1 w10: v1(1022.87,635.47) 1023.16,635.18 1023.16,458.29 ; v1(1037,390.4) 1037,393.02 1023.16,406.87 1023.16,458.29 ; v1(1040,440) 1040,441.45 1023.16,458.29
  Bottom Layer w10: F1.1 1000.4,390.4 v1(1037,390.4)
NetJ2_A6: J2.A6 J2.B6 R4.1 | length 249.7
  Top Layer w10: J2.A6 1094.25,531.06 1068.94,531.06 1052.01,547.99 1049.99,547.99 1049.99,549.84 1048.68,551.15 1048.68,553.01 1064.29,568.62 1094.25,568.62 J2.B6
  Bottom Layer w10: v1(1045.51,549.84) 1159.12,549.84 1170,560.72 R4.1
NetJ2_A7: J2.A7 J2.B7 R5.1 | length 153.3
  Top Layer w10: J2.B7 1096.06,511.38 1126.72,511.38 1136.1,520.75 v1(1138.72,520.75) 1136.86,522.61 1136.86,529.72 1121.52,545.06 1116.67,545.06 1112.8,548.94 1096.06,548.94 J2.A7
  Bottom Layer w10: v1(1138.72,520.75) 1159.12,520.75 1170,509.88 R5.1
NetLS1_P: LS1.P R8.2 | length 99.1
  Top Layer w10: LS1.P 657.6,149.17 657.6,171.38 690,203.78 R8.2
NetPAD3_1: PAD5.44 U5.51 | length 1128.8
  Top Layer w10: v1(679.21,761.75) 698.39,780.94 698.39,830.6 U5.51
  Layer 1 w10: v1(679.21,761.75) 681.79,761.75 861.38,582.16 861.38,455.06 948.84,367.6 948.84,192.27 935.35,178.78 885.53,178.78 770,63.25 v1(770,-18.55)
  Bottom Layer w10: PAD5.44 v1(770,-18.55)
NetPAD4_1: PAD4.44 U5.52 | length 1053.8
  Top Layer w10: U5.52 679.06,795.02 674.28,790.24 674.28,785.18 621.16,732.06 621.16,709.51 683.11,647.56 684.45,647.56 748.26,583.75 v1(750,583.75)
  Bottom Layer w10: PAD4.44 751.16,-22.17 751.16,120.38 810,179.23 810,523.75 v1(750,583.75)
NetPAD7_1: PAD8.44 U5.54 | length 979.2
  Top Layer w10: v1(545.12,986.11) 545.12,983.49 561.12,967.5 561.12,950.4 574.91,936.6 608.14,936.6 639.69,905.06 U5.54
  Bottom Layer w10: PAD8.44 45.21,970 418.2,970 434.32,986.11 v1(545.12,986.11)
NetPAD8_1: PAD7.44 U5.53 | length 971.7
  Top Layer w10: v1(437.93,1009.53) 555.01,1009.53 659.37,905.17 U5.53
  Bottom Layer w10: PAD7.44 -72.85,871.74 39.41,984 412.41,984 v1(437.93,1009.53)
NetR2_1: R2.1 U1.4 | length 77.7
  Bottom Layer w10: R2.1 826.73,763.27 U1.4
NetR8_1: R8.1 U5.61 | length 756.9
  Top Layer w10: U5.61 501.89,689.69 v1(524.21,667.36) ; v1(632.16,218.26) 634.01,220.12 639.41,220.12 690,270.71 R8.1
  Layer 1 w10: v1(524.21,667.36) 524.21,588.3 521.57,585.66 521.57,509.21 640,390.79 640,309.76 632.16,301.92 v1(632.16,218.26)
NetR9_2: R9.2 SW1.2 U5.60 | length 1027.4
  Top Layer w10: SW1.2 -92.52,660.41 -77.83,675.09 22.32,675.09 62.82,715.6 v1(133.6,715.6) ; U5.60 521.57,751.05 541.26,731.36 v1(541.26,704.83)
  Layer 1 w10: v1(133.6,715.6) 259.43,715.6 302.18,672.84 456.98,672.84 488.96,704.83 v1(541.26,704.83)
  Bottom Layer w10: R9.2 -25.08,759.37 34.29,700 83.14,700 98.73,715.6 v1(133.6,715.6)
NetR13_2: R13.2 U5.2 | length 1162.5
  Top Layer w10: v1(329.24,800) 384.62,800 420.34,764.28 420.34,751.94 411.61,743.2 410.7,743.2 405.92,738.43 U5.2 ; R13.2 v1(930,200.08)
  Layer 1 w10: v1(329.24,800) 496.65,800 930,366.65 v1(930,200.08)
SBA1: R6.2 U2.12 U5.26 | length 863
  Top Layer w10: R6.2 240,169.37 240,132.31 259.69,112.63 ; U2.12 259.69,115.34 272.69,128.35 293.92,128.35 v4(295.77,130.2) ; v1(600,290) 620,310 U5.26
  Layer 1 w10: v1(292.73,247.26) 292.73,244.64 282.59,234.49 282.59,217.41 322.33,177.67 372.42,177.67 v1(420.4,225.65)
  Layer 2 w10: v1(292.73,247.26) 324.99,215 324.99,159.42 v4(295.77,130.2) ; v1(420.4,225.65) 421.04,225.01 421.04,200.81 451.85,170 480,170 v1(600,290)
SBA2: R11.2 U3.6 U5.27 | length 607
  Top Layer w10: U3.6 470.08,40.16 ; R11.2 500.16,40.16 470.08,40.16 ; U5.27 639.69,272.68 570.99,203.99 570.99,30.99 541.85,1.85 480,1.85 470.08,11.77 470.08,40.16
SBA3: U2.13 U3.2 U5.21 | length 676.3
  Top Layer w10: v1(220,125.43) 239.92,105.51 U2.13@239.92,90.28 ; v1(340,57.84) 340.76,57.84 357.95,40.66 379.5,40.66 U3.2 ; v2(502.33,307.23) 502.33,307.35 518.45,323.46 518.45,330.54 521.57,333.66 U5.21
  Layer 1 w10: v1(220,125.43) 254.17,91.26 254.17,81.18 295.34,40 323.82,40 340,56.18 v1(340,57.84) 341.66,57.84 433.73,149.91 433.73,195.79 511.51,273.58 511.51,283.58 503.43,291.65 503.43,306.13 v2(502.33,307.23)
SBA4: U2.1 U3.5 U5.22 | length 866.2
  Top Layer w10: v1(155.12,66.28) 156.63,66.28 169.88,79.53 U2.1 ; U3.5 429.69,0.33 v1(440,-10) ; v2(533.78,302.75) 534.88,303.85 534.88,324.24 541.26,330.63 U5.22
  Layer 1 w10: v1(155.12,66.28) 157.74,66.28 171,79.53 201.04,79.53 313.25,-32.68 415.87,-32.68 439.28,-9.28 485.15,36.59 485.15,227.41 533.78,276.05 v2(533.78,302.75)
SBA5: U2.14 U3.4 U5.23 | length 861.7
  Top Layer w10: v1(170.76,106.68) 171.3,106.14 204.37,106.14 U2.14@220.24,90.28 ; v1(407.25,-13.84) 407.25,-11.22 410,-8.47 U3.4 ; v2(560,299.67) 560.6,300.27 560.6,389.65 U5.23
  Layer 1 w10: v1(170.76,106.68) 171.91,107.84 205.59,107.84 291.27,22.16 387.84,22.16 394.91,15.09 394.91,1.11 407.25,-11.22 v1(407.25,-13.84)
  Bottom Layer w10: v1(407.25,-13.84) 445.01,23.92 445.01,35.01 480.93,70.93 490.93,70.93 560,140 v2(560,299.67)
SBA6: U2.4 U5.15 | length 706
  Top Layer w10: v1(142.75,-12.93) 145.37,-12.93 159.57,1.27 170.76,1.27 189.96,20.47 U2.4 ; v2(303.26,482.52) U5.15
  Layer 1 w10: v1(142.75,-12.93) 142.75,47.27 136.28,53.75 136.28,98.85 240,202.57 240,290 258.7,308.7 258.7,449.32 290.8,481.42 302.16,481.42 v2(303.26,482.52)
SBA7: U2.9 U5.16 | length 587.8
  Top Layer w10: U2.9@290.12,40.24 295.77,40.24 321.81,66.28 321.81,78.78 v1(340,96.98) ; v2(310,440.42) 326.17,456.59 327.83,456.59 334.08,462.83 U5.16
  Layer 1 w10: v2(310,440.42) 310,387.15 300.22,377.37 300.22,307.8 255.5,263.08 255.5,136.44 307.6,84.35 324.75,84.35 337.38,96.98 v1(340,96.98)
SCLD: PAD2.44 U5.58 | length 1093
  Top Layer w10: U5.58 560.94,766.87 601.16,726.66 v1(601.16,581)
  Layer 1 w10: v1(500.05,-76.8) 536.82,-76.8 654,40.38 654,502.96 601.16,555.8 v1(601.16,581)
  Bottom Layer w10: v1(500.05,-76.8) 501.79,-75.06 558.26,-75.06 PAD2.44
SDAC: PAD1.44 U5.59 | length 1068.3
  Top Layer w10: U5.59 541.26,766.75 573.21,734.8 573.21,724.26 579.47,717.99 579.47,672.84 v1(578.42,671.78)
  Layer 2 w10: v1(578.42,671.78) 579.47,670.73 579.47,347.45 v1(935.07,-8.15)
  Bottom Layer w10: PAD1.44 v1(935.07,-8.15)
ST_CLOCK: pad.33 U5.49 | length 519.3
  Top Layer w10: pad.33@470,1220 470,1131 574.23,1026.77 574.23,1018.35 685.56,907.02 718.37,907.02 738.11,887.28 U5.49
ST_DATA: pad.40 U5.46 | length 722.9
  Top Layer w10: pad.40 699.63,1070.37 699.63,1061.99 735.23,1026.39 735.23,1021.45 750.65,1006.03 784.86,1006.03 811.49,979.4 811.49,888.71 835.17,865.03 835.17,850.64 841.62,844.19 856.01,844.19 907.96,792.25 907.96,759.41 867.28,718.74 U5.46
ST_NRST: C21.2 pad.30 R10.2 SW2.2 U5.7 | length 1580.9
  Top Layer w10: v1(-137.8,363.8) -137.8,366.42 -128.86,375.35 -128.86,404.82 -114.17,419.5 SW2.2 ; pad.30 172.75,1197.25 v1(172.75,1106.16) ; v1(282.24,647.24) 284.09,645.39 306.69,645.39 312.08,640 U5.7
  Layer 1 w10: v1(-137.8,363.8) -137.8,453.82 108.39,700 ; v1(172.75,1106.16) 170.13,1106.16 156.29,1120 140,1120 108.39,1088.39 108.39,700 ; v1(282.24,647.24) 161.14,647.24 108.39,700
  Bottom Layer w10: v1(-137.8,363.8) -125.27,376.32 -48.7,376.32 ; C21.2 -48.7,376.32 ; R10.2 -30.08,441.26 -48.7,422.64 -48.7,376.32
TELNET: J1.1 U5.43 | length 644.1
  Top Layer w10: v1(640,724.26) 666.99,697.27 666.99,684.82 692.12,659.69 U5.43
  Layer 1 w10: v1(467.52,1028.37) 467.52,991.14 542.74,915.91 542.74,821.51 v1(640,724.26)
  Bottom Layer w10: v1(467.52,1028.37) 469.37,1030.22 469.37,1087.17 J1.1
UART3_RX: pad.36 U5.30 | length 1087
  Top Layer w10: v1(630.1,620.1) 631.95,618.25 651.75,618.25 698.74,571.26 U5.30 ; pad.36@810,1220 822.16,1207.84 v1(822.16,1116.46)
  Bottom Layer w10: v1(630.1,620.1) 631.95,621.95 631.95,641.9 640,649.94 640,675.55 621.16,694.39 621.16,778.5 568.93,830.73 568.93,914.83 581.66,927.55 606.82,927.55 636.42,957.16 736.66,957.16 822.16,1042.65 v1(822.16,1116.46)
UART3_TX: pad.35 U5.29 | length 1092.7
  Top Layer w10: v1(640.85,598.99) 679.06,560.79 U5.29 ; pad.35@710,1220 778.35,1151.65 v1(778.35,1103.3)
  Bottom Layer w10: v1(640.85,598.99) 638.99,600.85 622.71,600.85 607.16,616.4 607.16,750.54 554.93,802.77 554.93,924.68 607.56,977.31 664.64,977.31 665.02,976.94 736.65,976.94 784.06,1024.35 784.06,1059.66 778.35,1065.37 v1(778.35,1103.3)
pads on no net: J1.P1 J1.P2 J2.A8 J2.B8 LS1.1 SW1.1 SW1.3 SW2.1 SW2.3 U1.1 U2.2 U2.3 U2.10 U2.11 U3.7 U4.1 U4.2 U5.3 U5.4 U5.8 U5.9 U5.10 U5.11 U5.17 U5.20 U5.24 U5.25 U5.28 U5.33 U5.34 U5.35 U5.36 U5.41 U5.42 U5.50 U5.55 U5.56 U5.57 U5.62
copper on no net: | length 1511.1
  Layer 1 w10: 227.38,814.6 304.09,737.89 432.94,737.89 ; 516.75,885.53 388.12,885.53 310.4,807.8 310.4,792.2 345.86,756.73 520.12,756.73 762.72,514.13 v1(762.72,401.95)
  Bottom Layer w10: 736.64,171.32 736.64,174.34 744.61,182.31 754.76,182.31 776.72,204.26 776.72,319.93 728.28,368.36 728.28,424.78 735.09,417.97 746.69,417.97 v1(762.72,401.95)

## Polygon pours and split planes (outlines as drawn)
GND on Layer 1 "GND_L02_P001" (solid, remove dead copper, pour order 1): -196.85,228.77 ccw(c-96.04,228.77) -167.32,157.48 cw(c-238.61,86.19) -137.8,86.19 -137.8,0 ccw(c0,0) 0,-137.8 1181.1,-137.8 ccw(c1181.1,0) 1318.9,0 1318.9,86.19 cw(c1419.71,86.19) 1348.43,157.48 ccw(c1277.14,228.77) 1377.95,228.77 1377.95,952.34 ccw(c1277.14,952.34) 1348.43,1023.62 cw(c1419.71,1094.91) 1318.9,1094.91 1318.9,1181.1 ccw(c1181.1,1181.1) 1181.1,1318.9 -0.17,1318.9 0,1318.9 ccw(c0,1181.1) -137.8,1181.1 -137.8,1094.91 cw(c-238.61,1094.91) -167.32,1023.62 ccw(c-96.04,952.34) -196.85,952.34
GND on Layer 2 "GND_L03_P002" (solid, remove dead copper, pour order 2): -196.85,228.77 ccw(c-96.04,228.77) -167.32,157.48 cw(c-238.61,86.19) -137.8,86.19 -137.8,0 ccw(c0,0) 0,-137.8 1181.1,-137.8 ccw(c1181.1,0) 1318.9,0 1318.9,86.19 cw(c1419.71,86.19) 1348.43,157.48 ccw(c1277.14,228.77) 1377.95,228.77 1377.95,952.34 ccw(c1277.14,952.34) 1348.43,1023.62 cw(c1419.71,1094.91) 1318.9,1094.91 1318.9,1181.1 ccw(c1181.1,1181.1) 1181.1,1318.9 -0.17,1318.9 0,1318.9 ccw(c0,1181.1) -137.8,1181.1 -137.8,1094.91 cw(c-238.61,1094.91) -167.32,1023.62 ccw(c-96.04,952.34) -196.85,952.34
GND on Bottom Layer "GND_L04_P003" (solid, remove dead copper, pour order 3): -196.85,228.77 ccw(c-96.04,228.77) -167.32,157.48 cw(c-238.61,86.19) -137.8,86.19 -137.8,0 ccw(c0,0) 0,-137.8 1181.1,-137.8 ccw(c1181.1,0) 1318.9,0 1318.9,86.19 cw(c1419.71,86.19) 1348.43,157.48 ccw(c1277.14,228.77) 1377.95,228.77 1377.95,952.34 ccw(c1277.14,952.34) 1348.43,1023.62 cw(c1419.71,1094.91) 1318.9,1094.91 1318.9,1181.1 ccw(c1181.1,1181.1) 1181.1,1318.9 -0.17,1318.9 0,1318.9 ccw(c0,1181.1) -137.8,1181.1 -137.8,1094.91 cw(c-238.61,1094.91) -167.32,1023.62 ccw(c-96.04,952.34) -196.85,952.34
GND on Top Layer "GND_L01_P000" (solid, remove dead copper, pour order 0): -196.85,228.77 ccw(c-96.04,228.77) -167.32,157.48 cw(c-238.61,86.19) -137.8,86.19 -137.8,0 ccw(c0,0) 0,-137.8 1181.1,-137.8 ccw(c1181.1,0) 1318.9,0 1318.9,86.19 cw(c1419.71,86.19) 1348.43,157.48 ccw(c1277.14,228.77) 1377.95,228.77 1377.95,952.34 ccw(c1277.14,952.34) 1348.43,1023.62 cw(c1419.71,1094.91) 1318.9,1094.91 1318.9,1181.1 ccw(c1181.1,1181.1) 1181.1,1318.9 -0.17,1318.9 0,1318.9 ccw(c0,1181.1) -137.8,1181.1 -137.8,1094.91 cw(c-238.61,1094.91) -167.32,1023.62 ccw(c-96.04,952.34) -196.85,952.34

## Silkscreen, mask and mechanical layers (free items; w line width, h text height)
Top Overlay:
  drawing of 2 lines, arcs and shapes, not listed
  text "DTA SCK 3V3 GND RST" at 600,1290 h23.62 r180
  text "GND 3V3 RX TX" at 1030,1290 h23.62 r180
  text "ARTYOM" at 1030,100 h39.37 r90
Bottom Overlay:
  text "5V" at 1030,1130 h39.37
Mechanical 1:
  lines w10: -0.17,1318.9 1181.1,1318.9 cw(c1181.1,1181.1) 1318.9,1181.1 1318.9,1094.91 ccw(c1419.71,1094.91) 1348.43,1023.62 cw(c1277.14,952.34) 1377.95,952.34 1377.95,228.77 cw(c1277.14,228.77) 1348.43,157.48 ccw(c1419.71,86.19) 1318.9,86.19 1318.9,0 cw(c1181.1,0) 1181.1,-137.8 0,-137.8 cw(c0,0) -137.8,0 -137.8,86.19 ccw(c-238.61,86.19) -167.32,157.48 cw(c-96.04,228.77) -196.85,228.77 -196.85,952.34 cw(c-96.04,952.34) -167.32,1023.62 ccw(c-238.61,1094.91) -137.8,1094.91 -137.8,1181.1 cw(c0,1181.1) 0,1318.9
